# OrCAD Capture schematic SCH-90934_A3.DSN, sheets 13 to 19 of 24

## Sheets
13 C-09 IO MUX: size A2
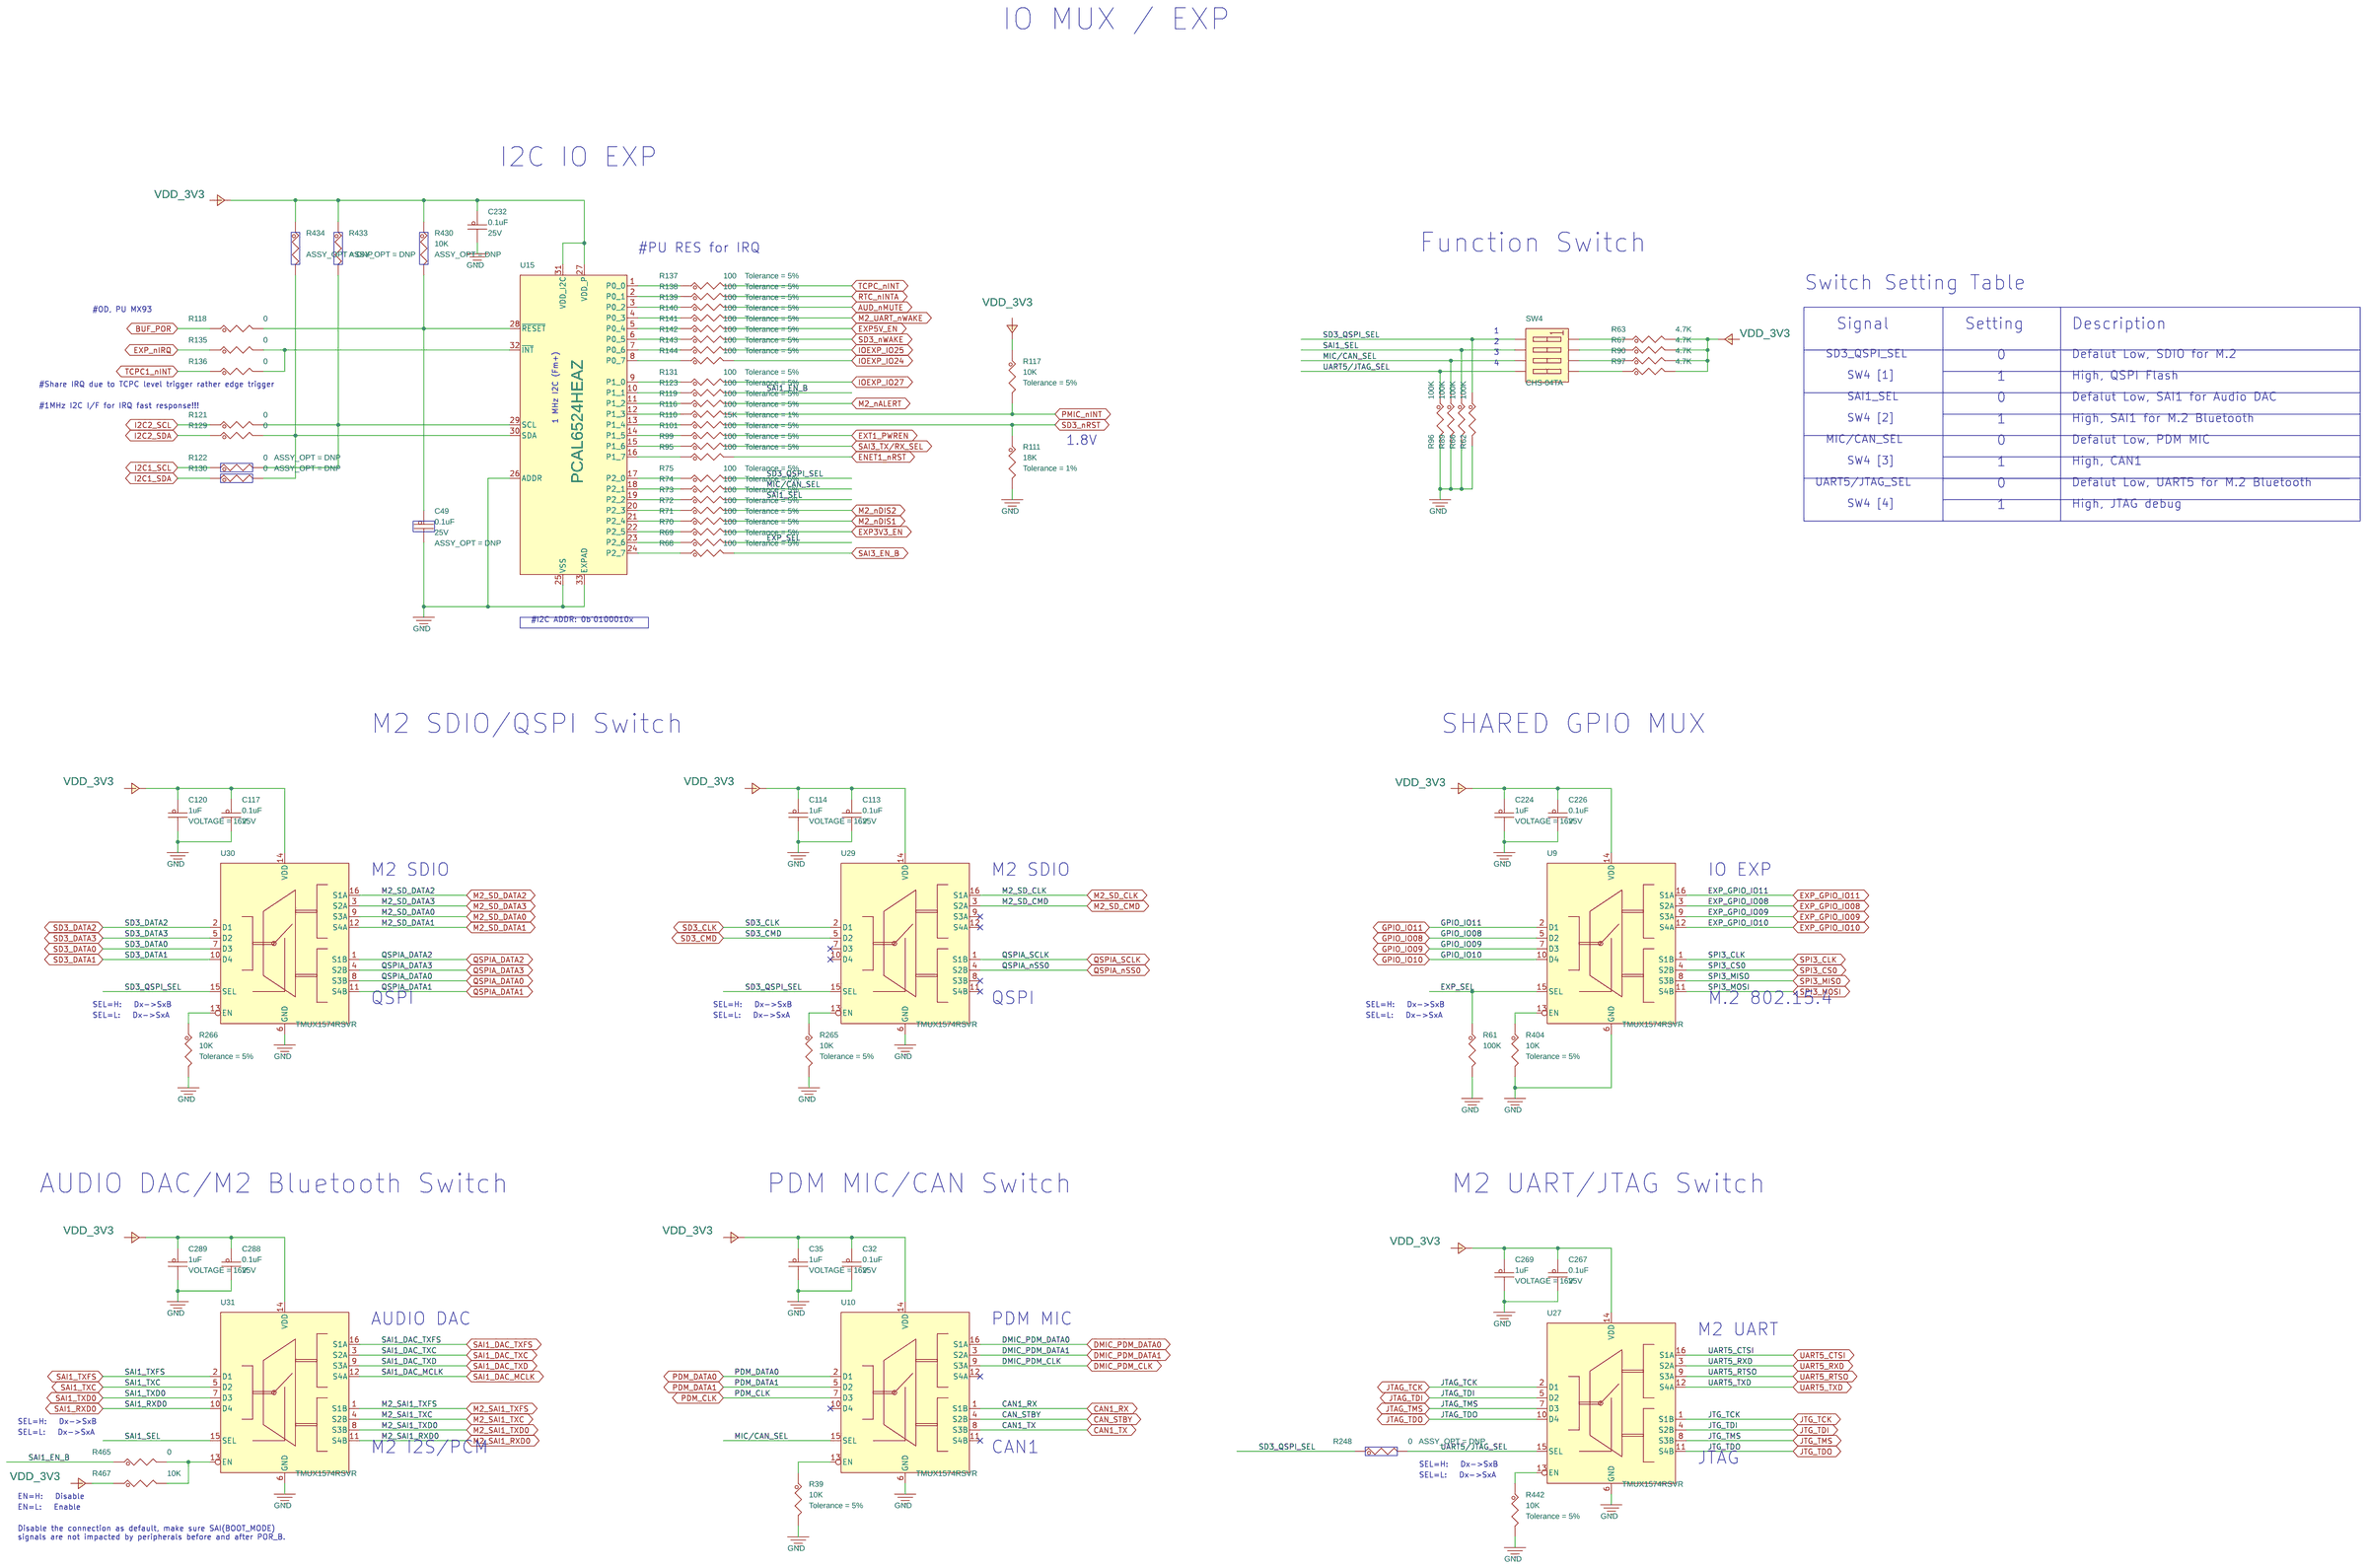
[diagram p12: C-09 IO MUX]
14 A-01 COVER: company: NXP Semiconductors
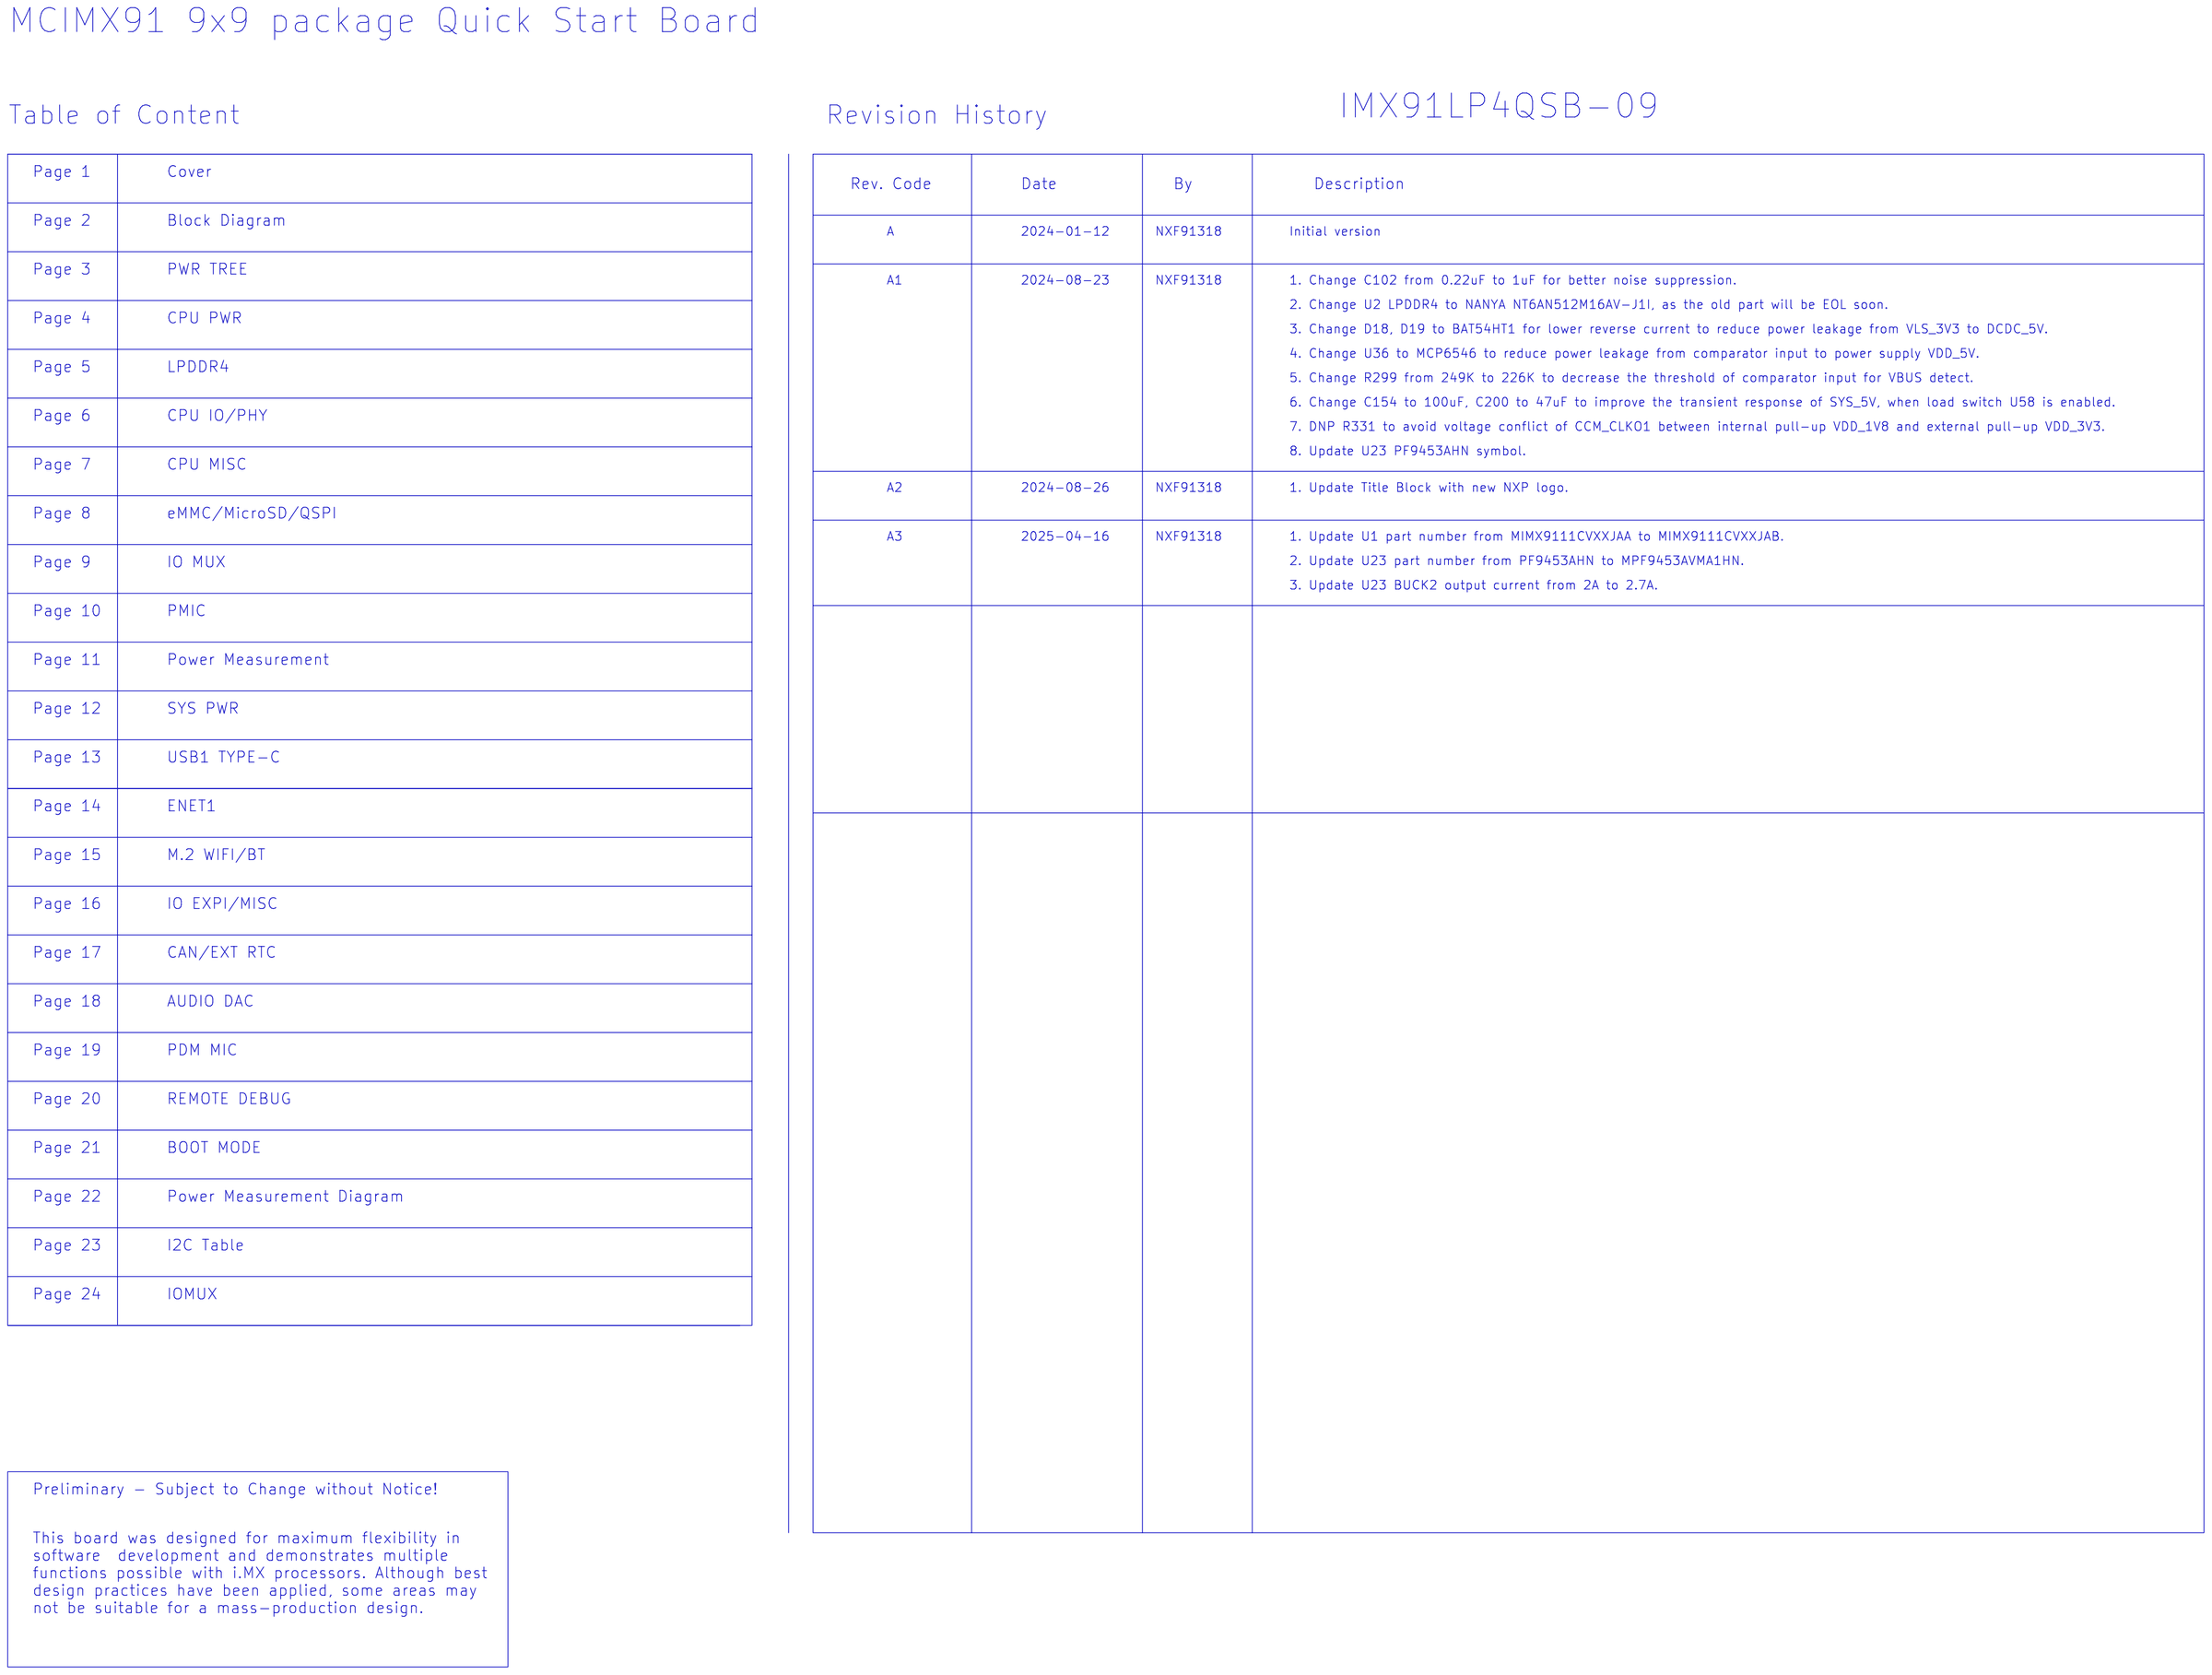
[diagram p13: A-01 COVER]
15 A-02 BLOCK DIAGRAM: company: NXP Semiconductors
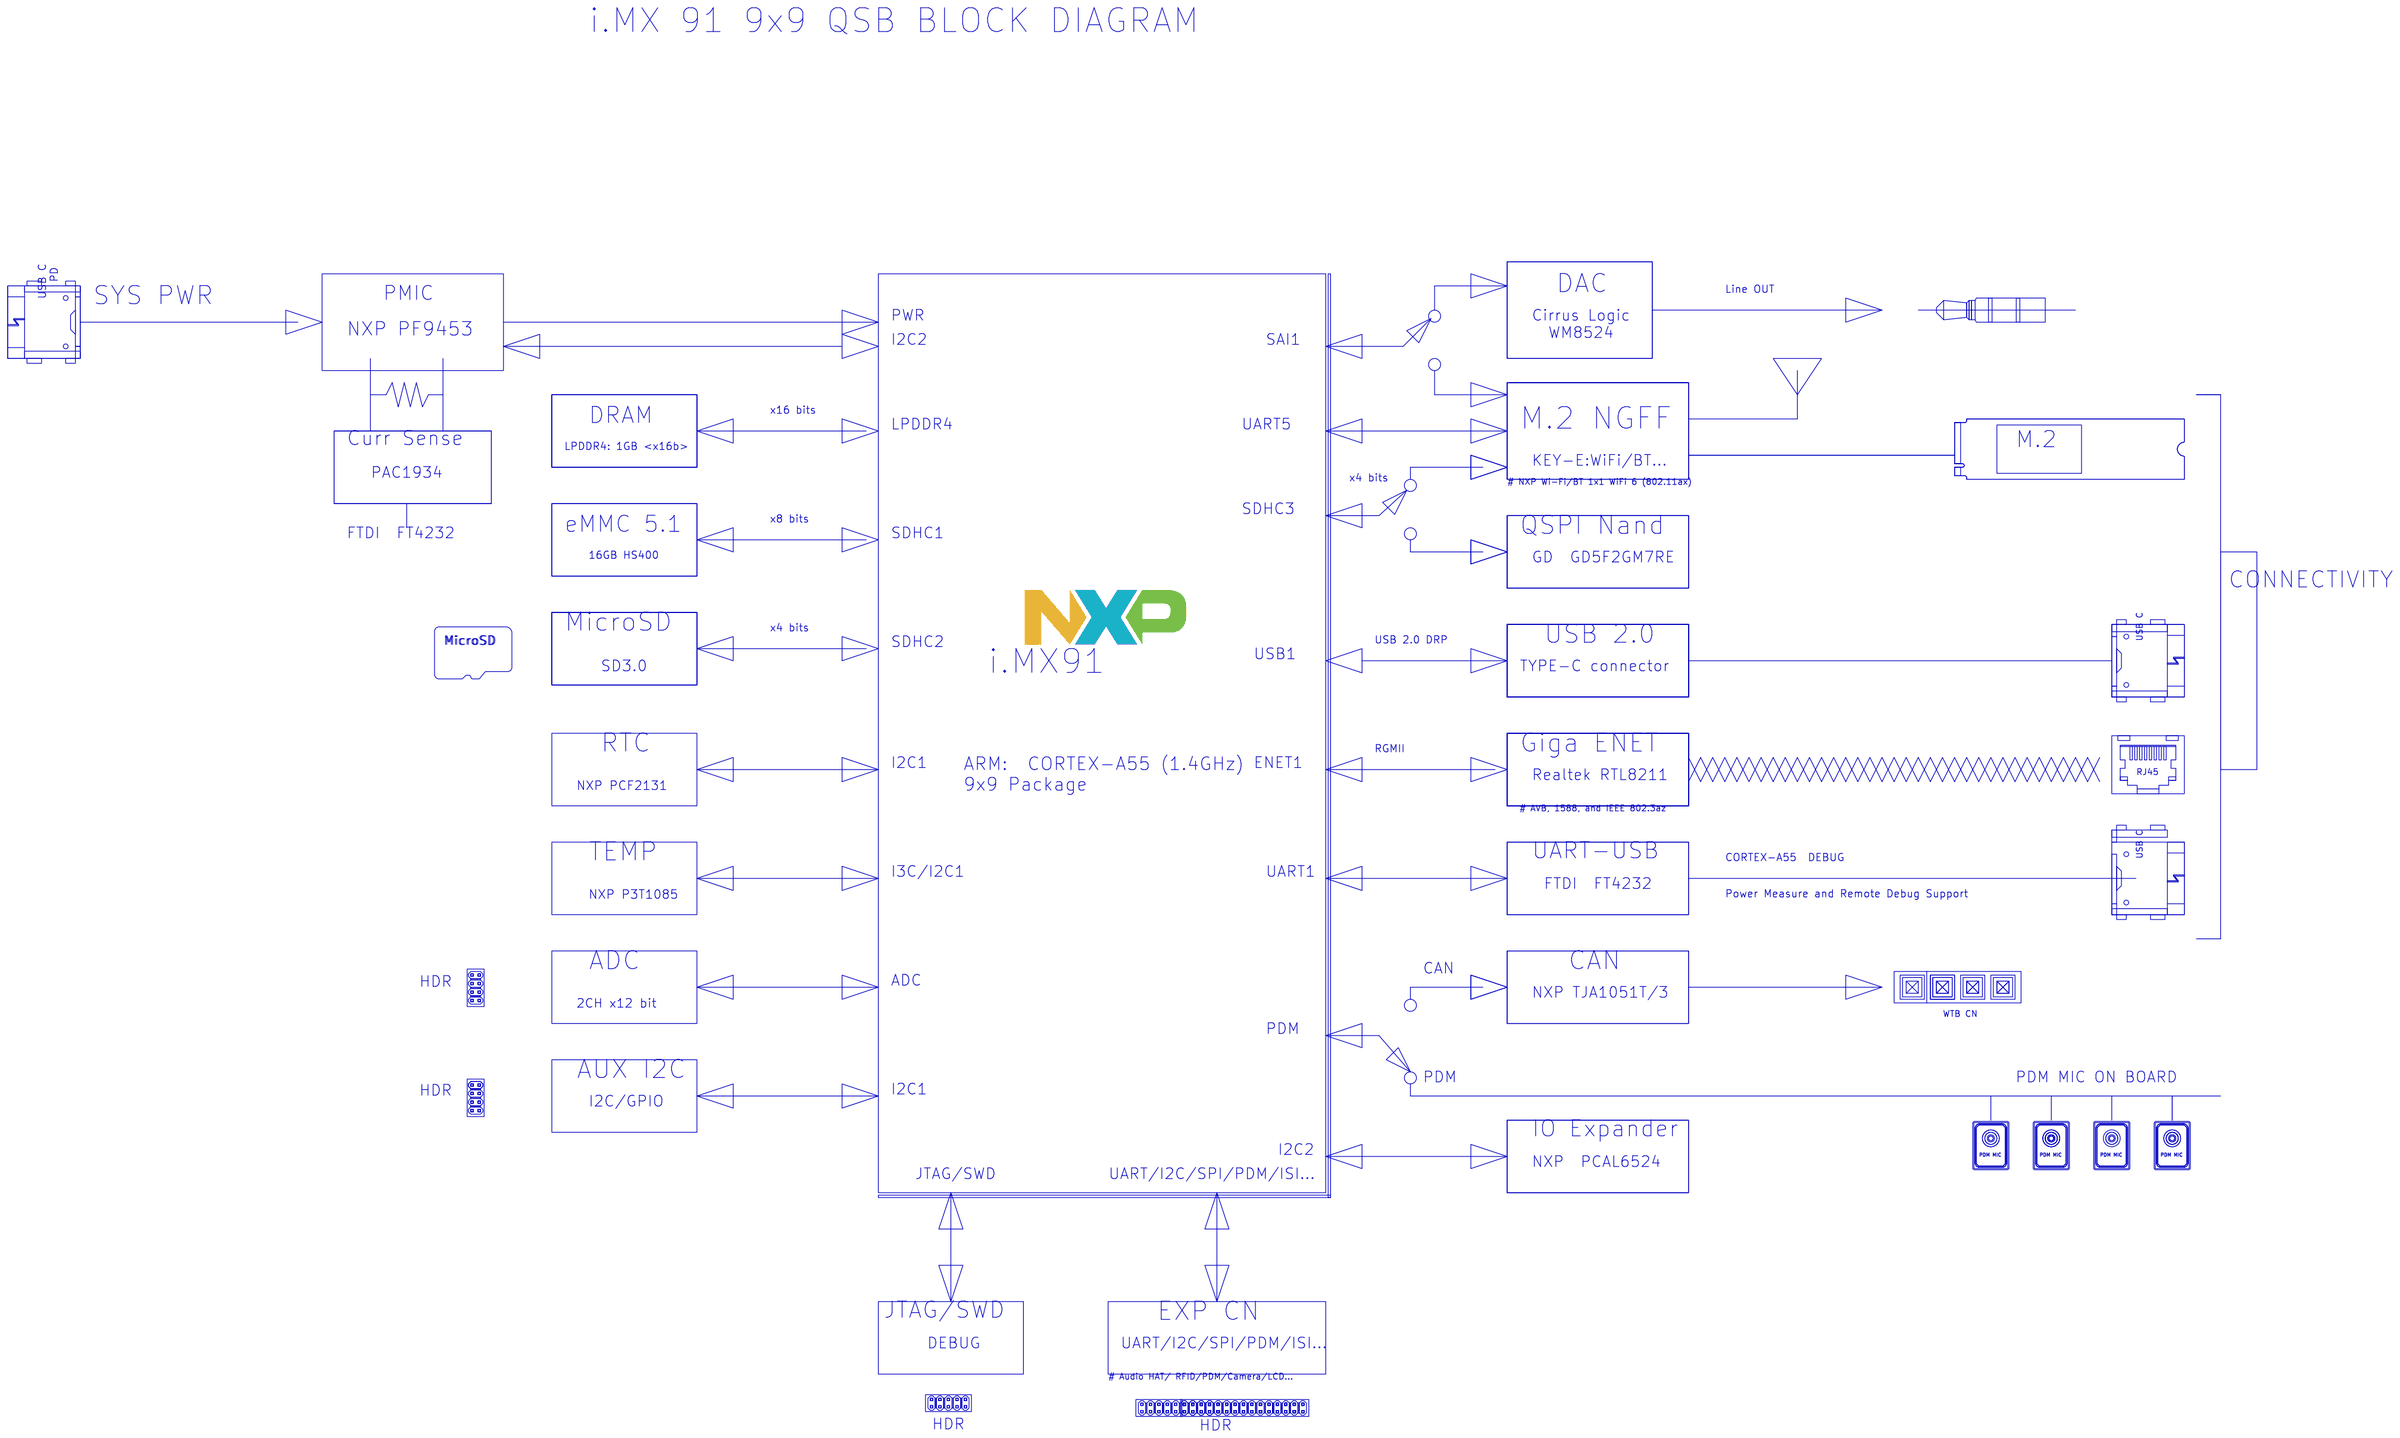
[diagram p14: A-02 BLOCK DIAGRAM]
16 A-03 PWR TREE: company: NXP Semiconductors
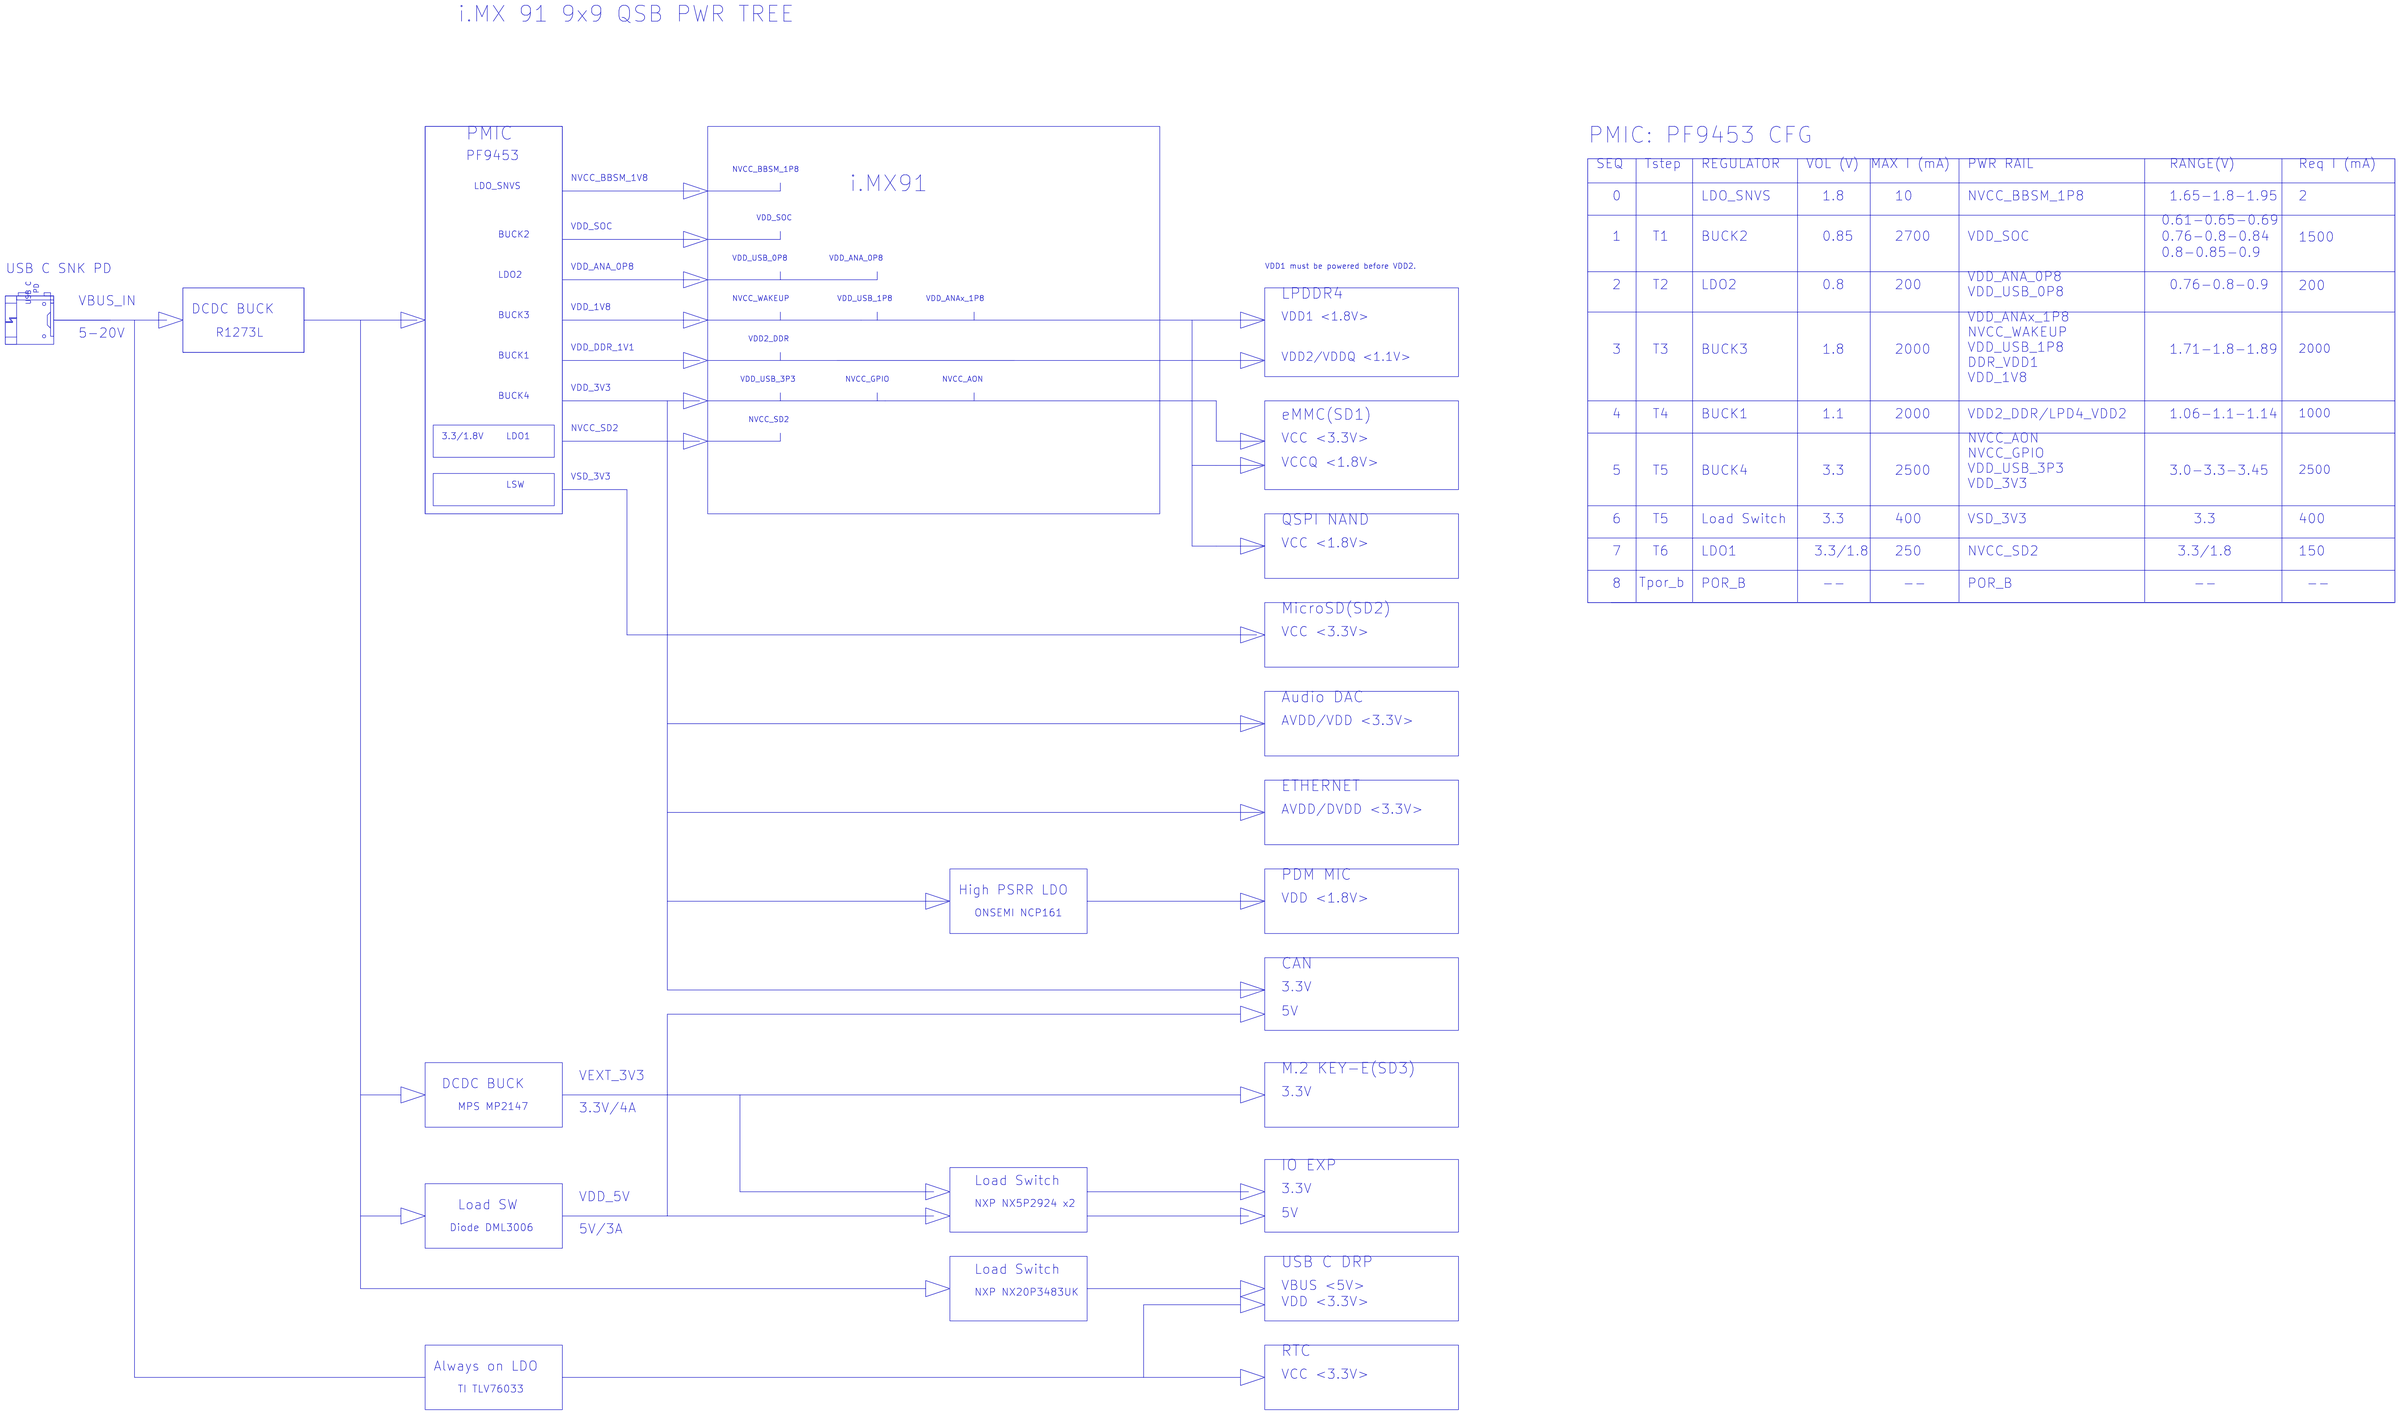
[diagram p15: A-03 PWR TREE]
17 C-04 CPU PWR: size C; company: NXP Semiconductors
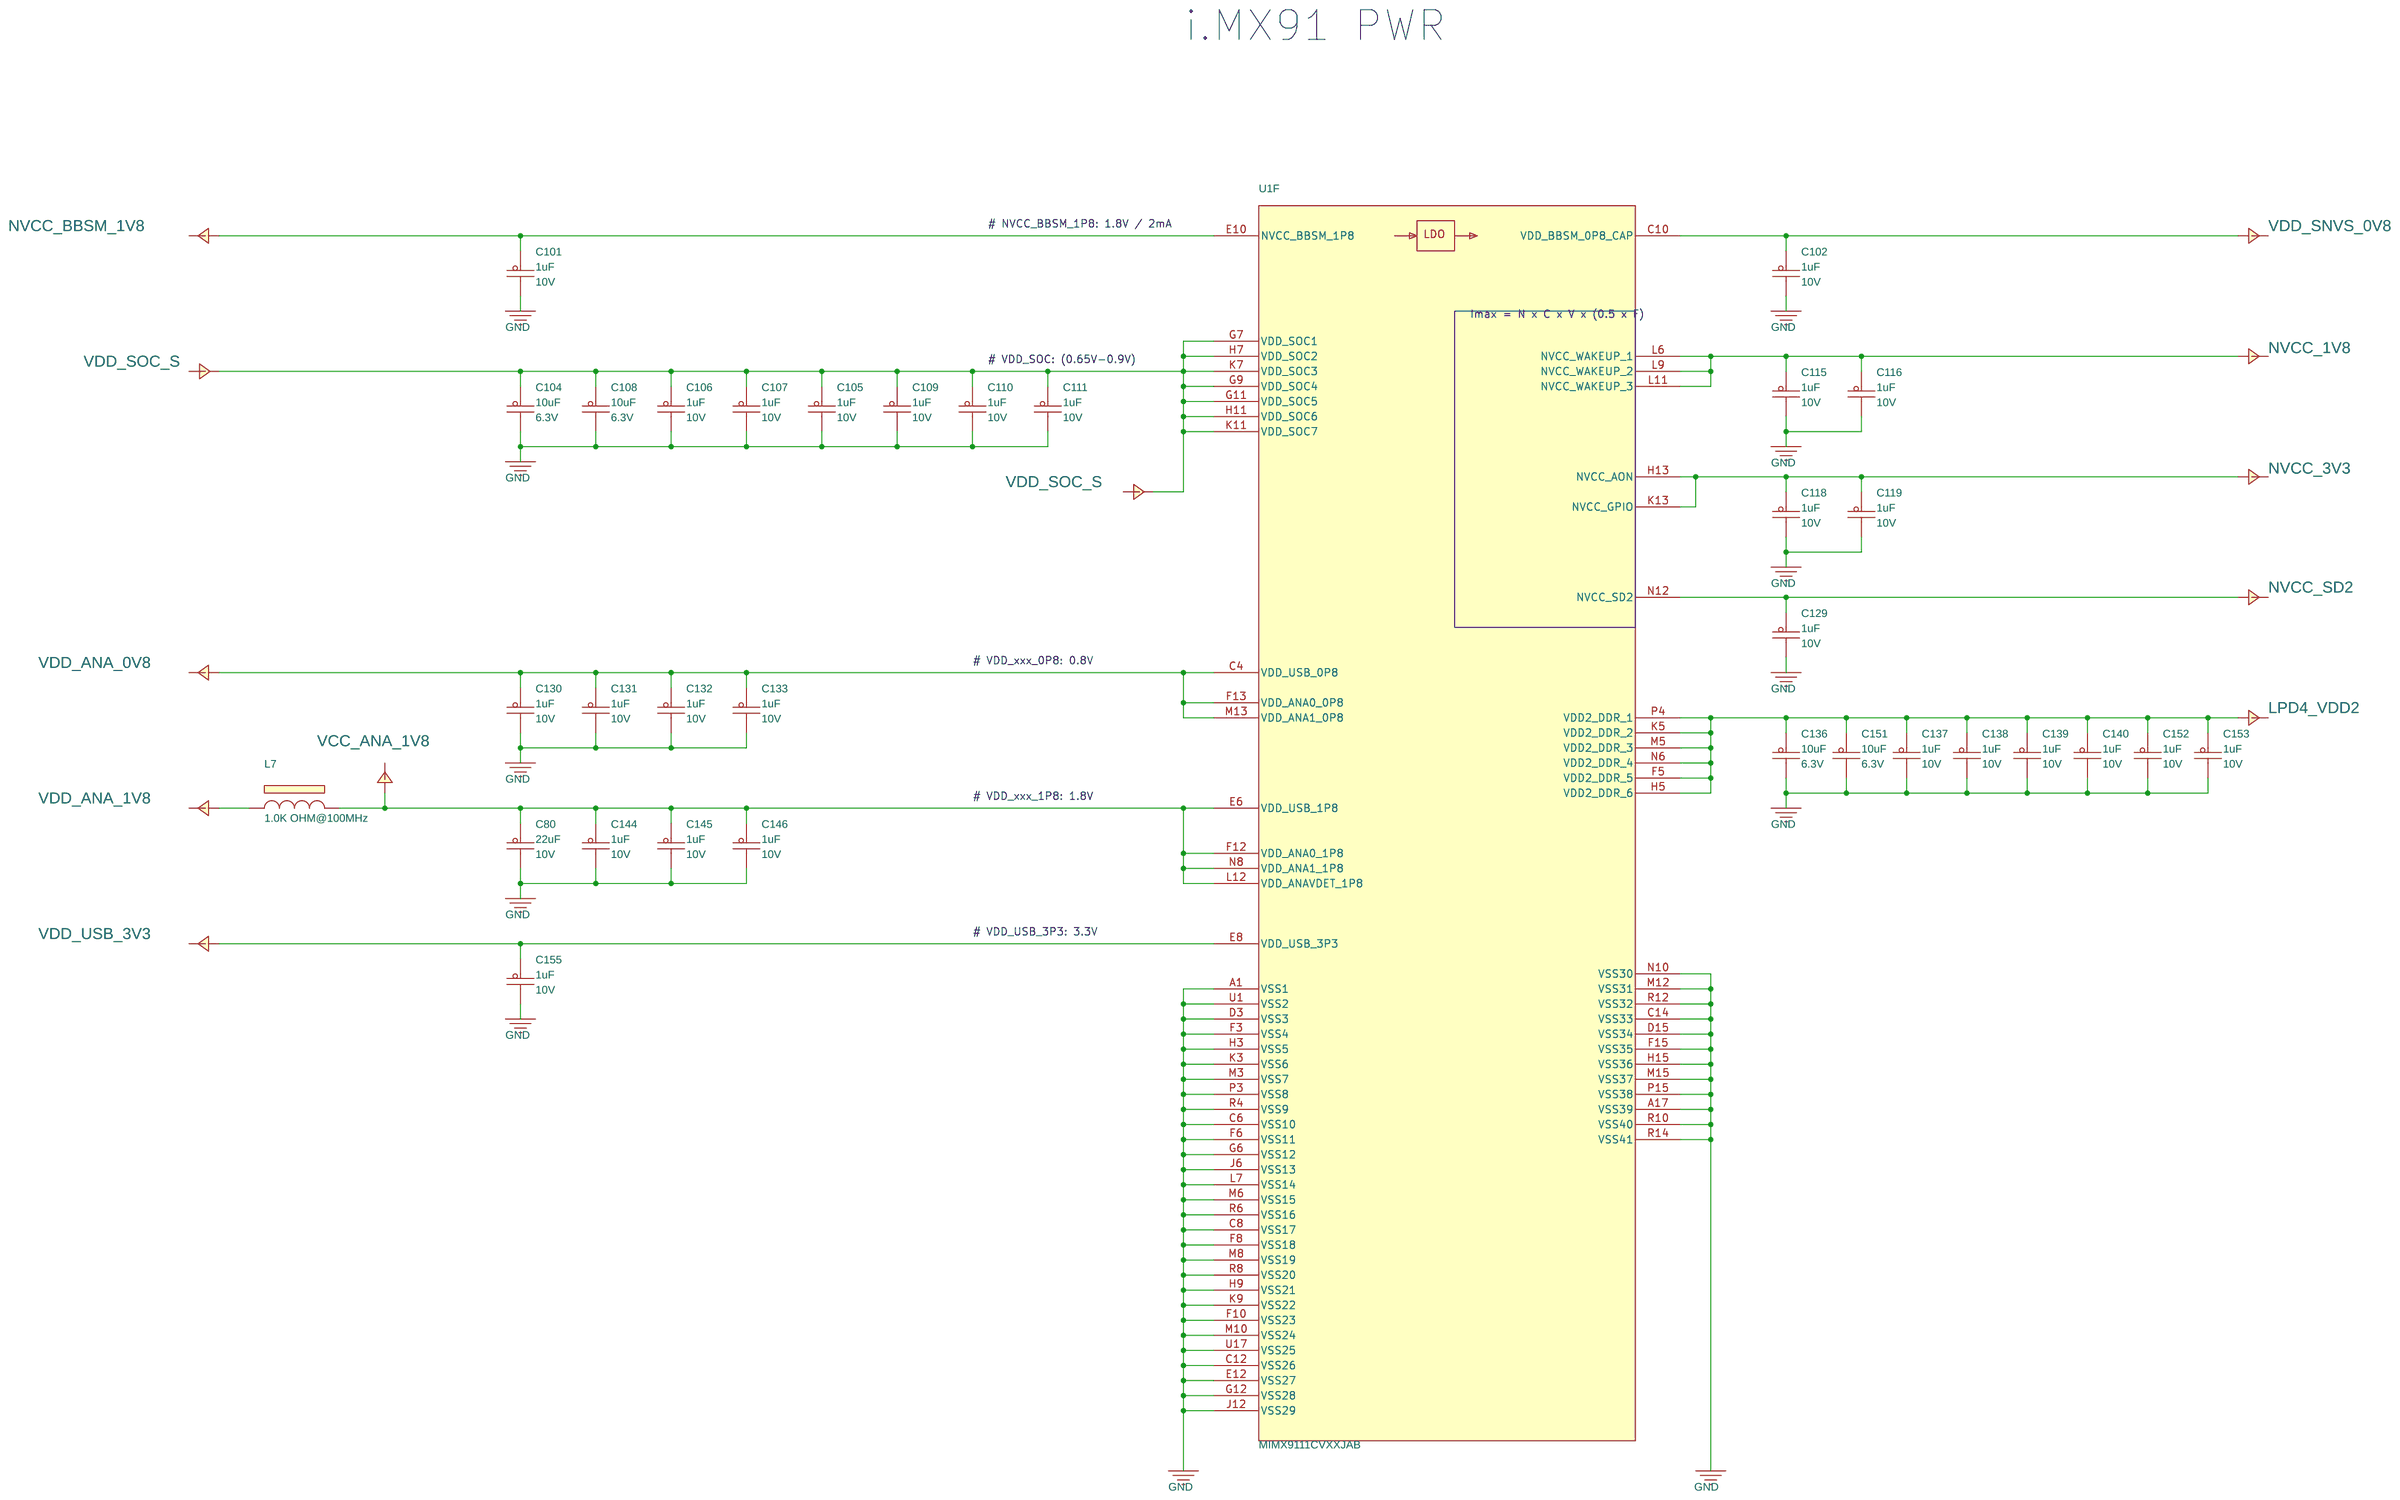
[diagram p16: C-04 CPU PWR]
18 C-05 LPDDR4: size C; company: NXP Semiconductors
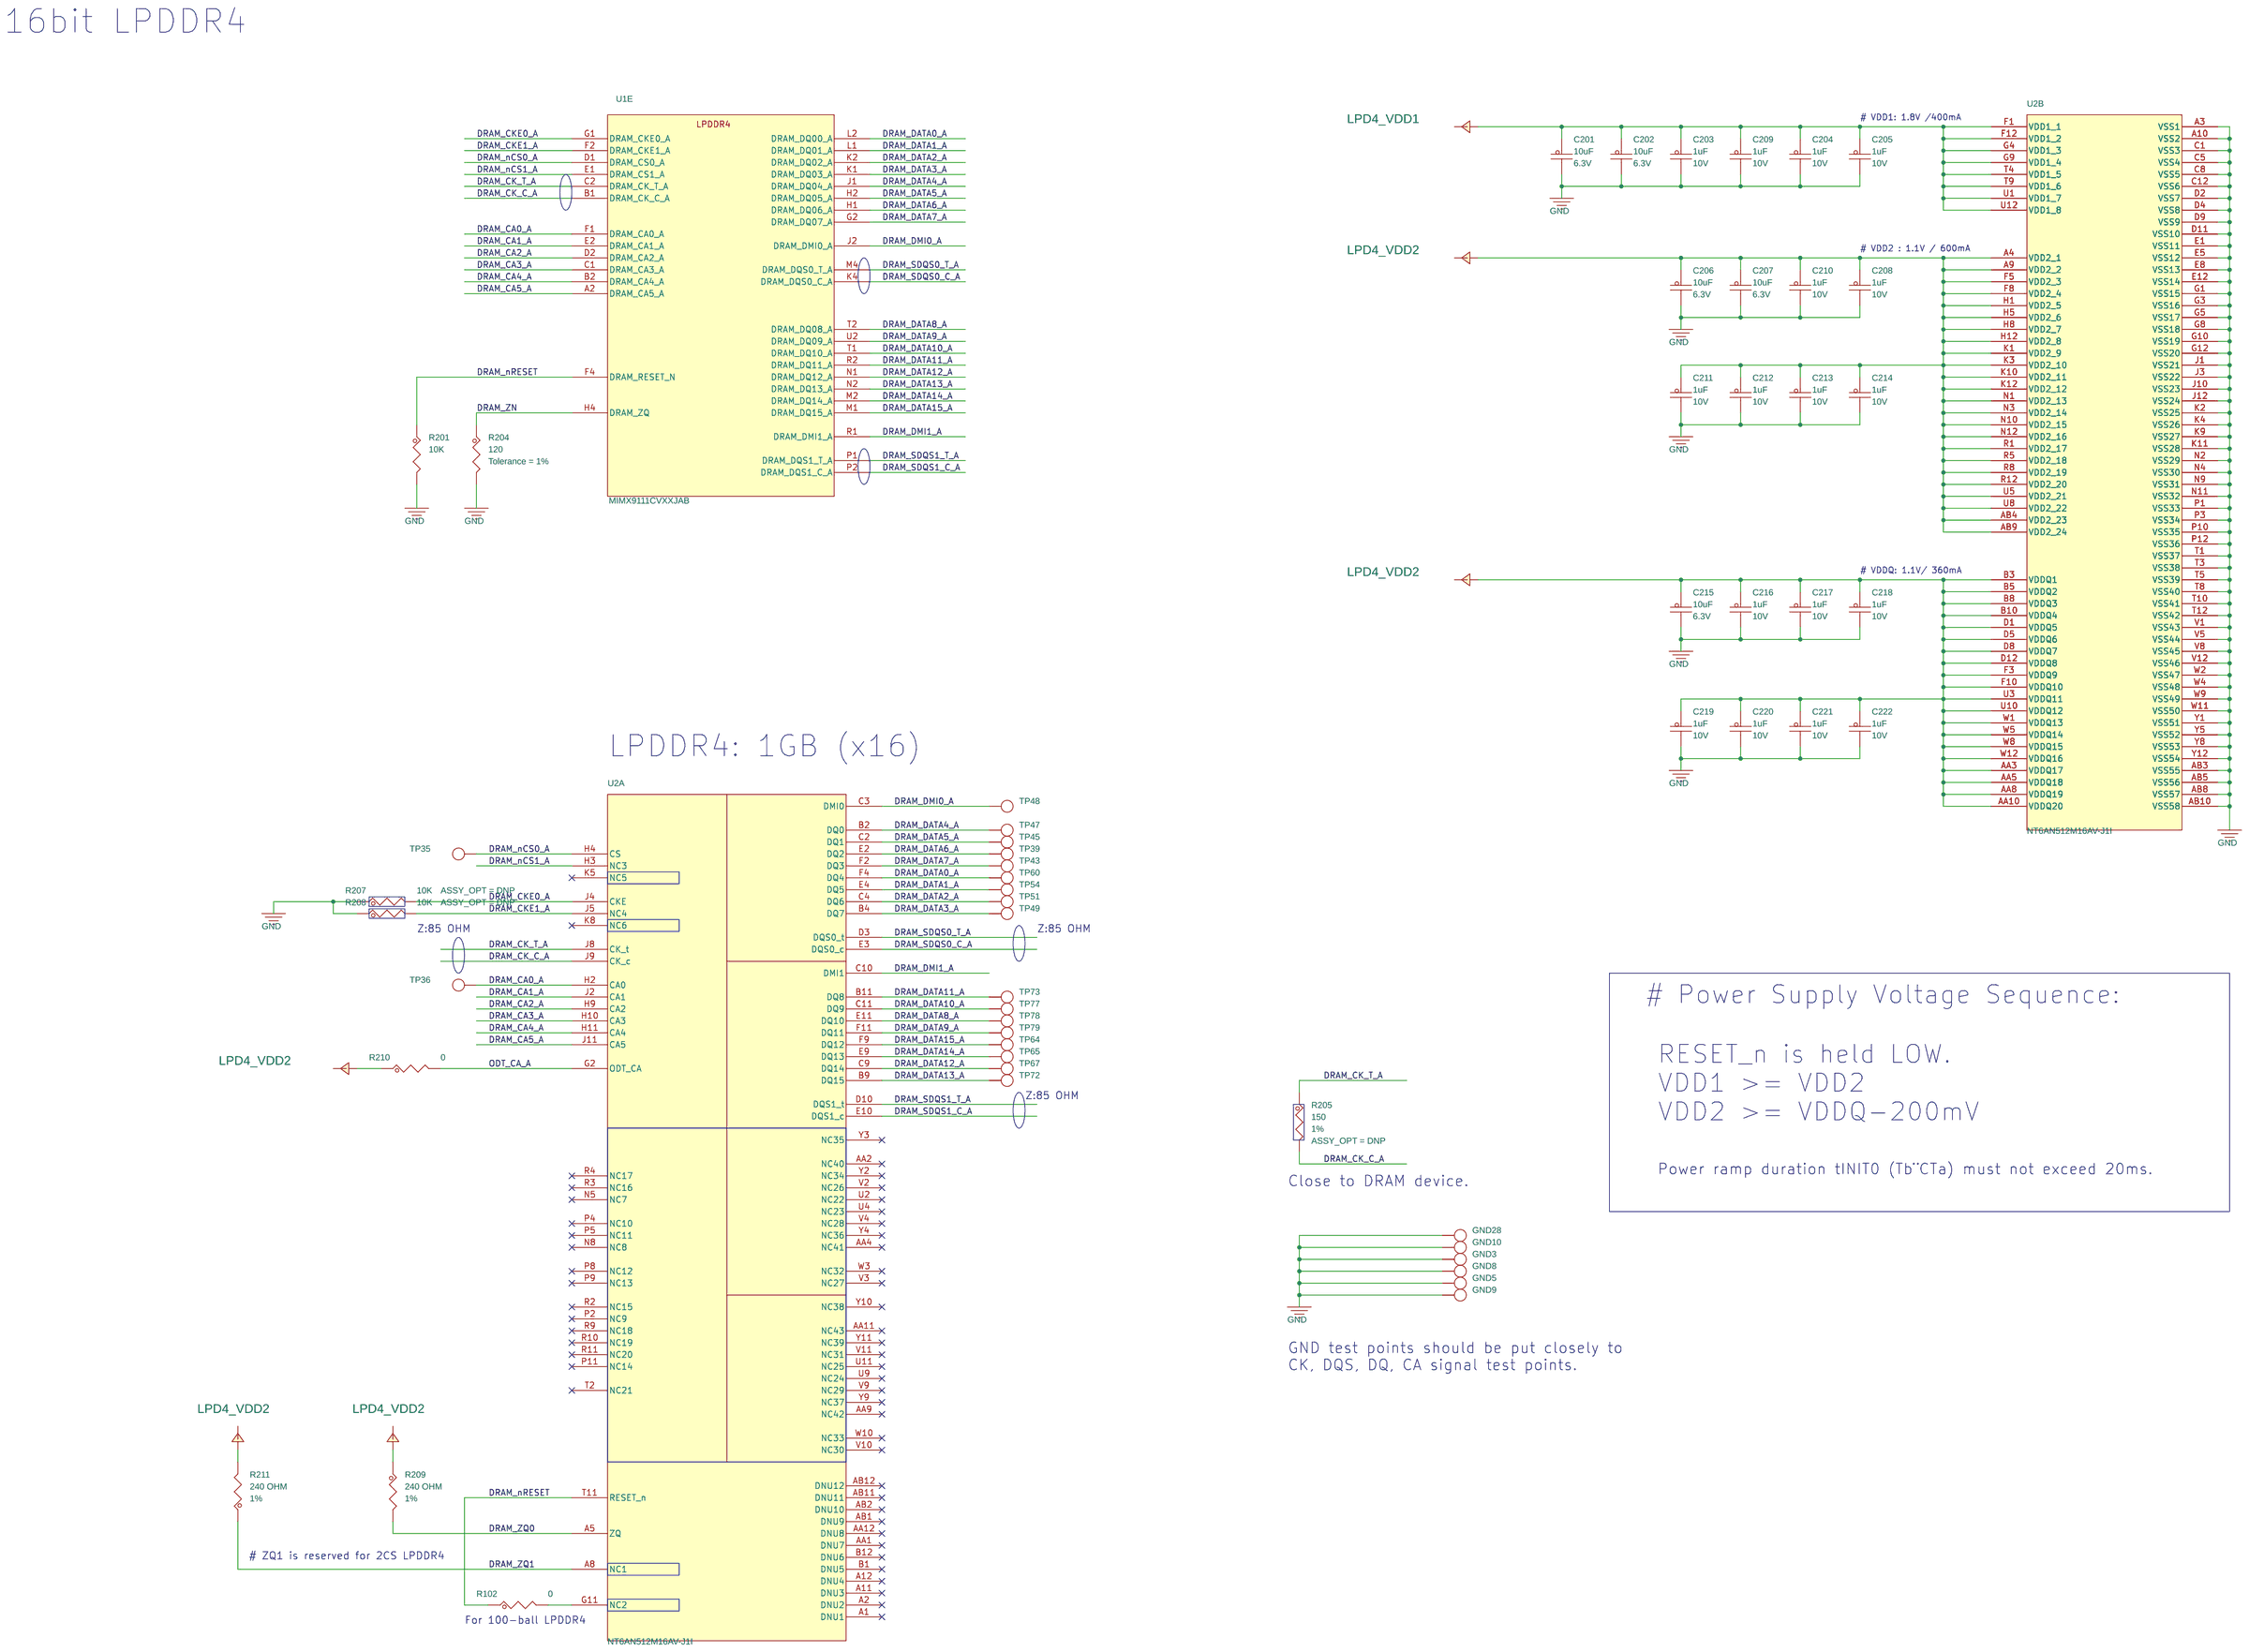
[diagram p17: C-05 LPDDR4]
19 C-10 PMIC: size C
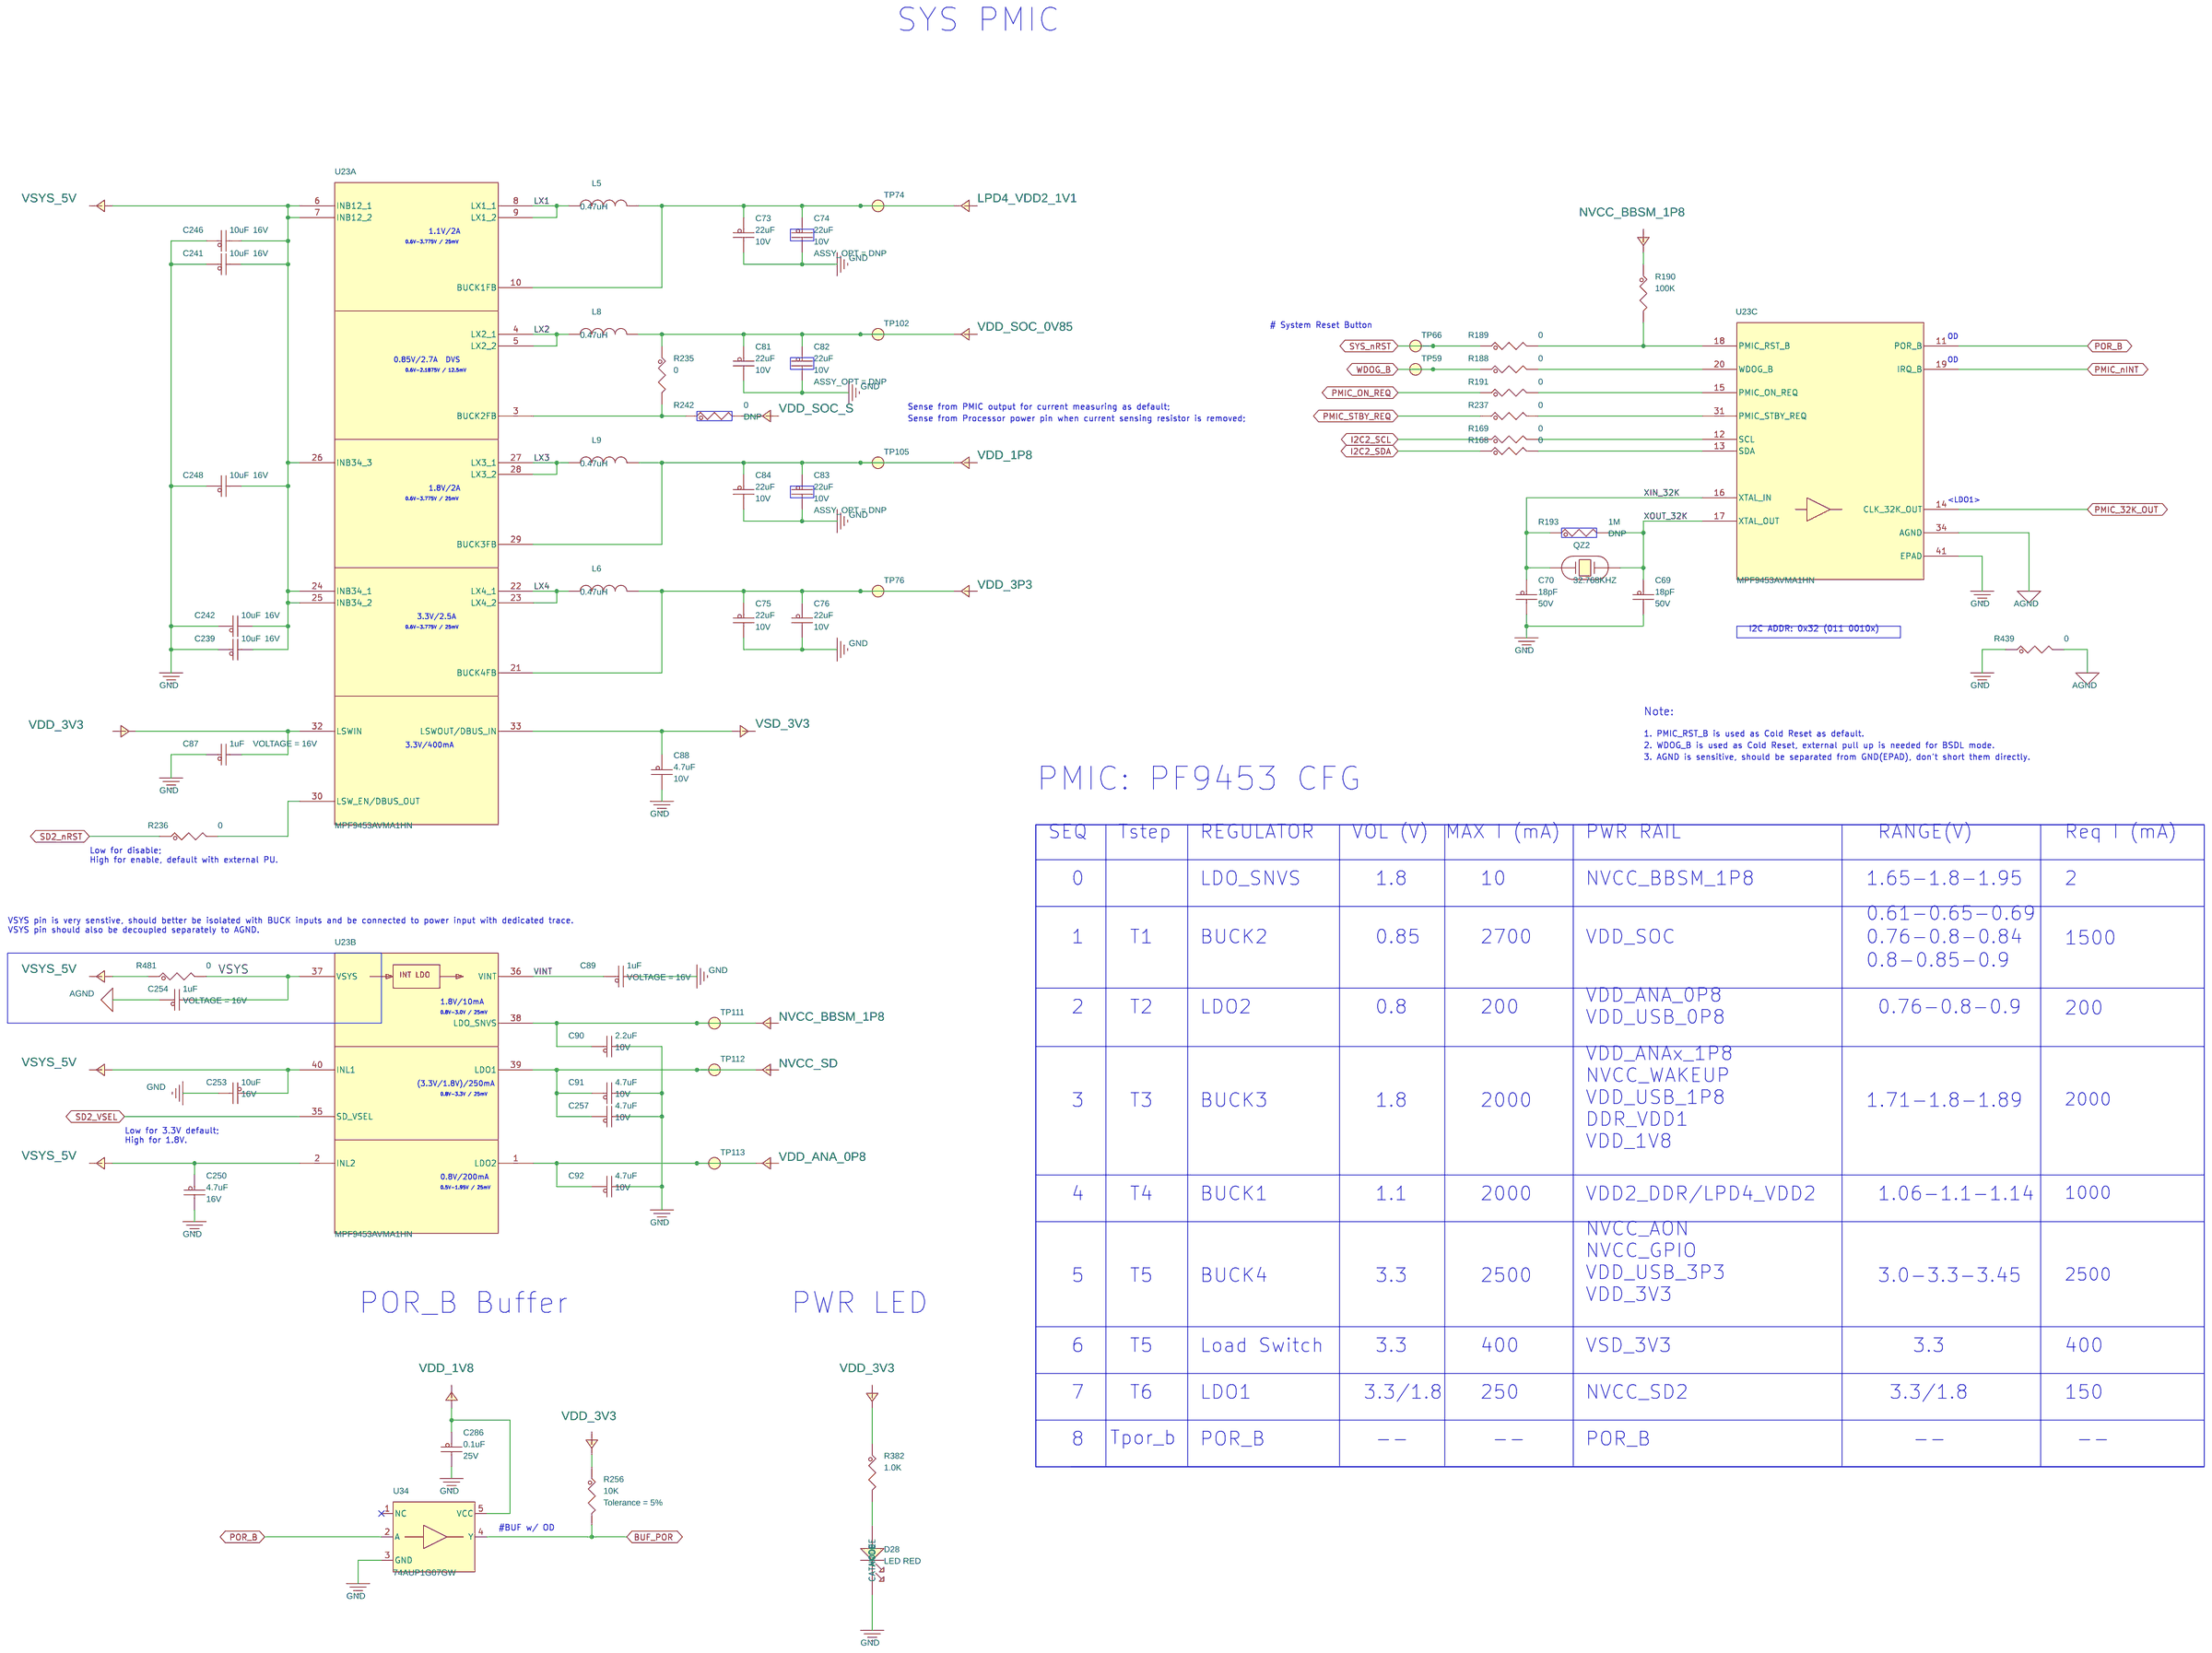
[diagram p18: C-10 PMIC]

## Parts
sheet C-04 CPU PWR
C80  22uF  [CC0603]
C101  1uF  [0201_CC]
C102  1uF  [0201_CC]
C104  10uF  [0402_cc_nsp]
C105  1uF  [0201_CC]
C106  1uF  [0201_CC]
C107  1uF  [0201_CC]
C108  10uF  [0402_cc_nsp]
C109  1uF  [0201_CC]
C110  1uF  [0201_CC]
C111  1uF  [0201_CC]
C115  1uF  [0201_CC]
C116  1uF  [0201_CC]
C118  1uF  [0201_CC]
C119  1uF  [0201_CC]
C129  1uF  [0201_CC]
C130  1uF  [0201_CC]
C131  1uF  [0201_CC]
C132  1uF  [0201_CC]
C133  1uF  [0201_CC]
C136  10uF  [0402_cc_nsp]
C137  1uF  [0201_CC]
C138  1uF  [0201_CC]
C139  1uF  [0201_CC]
C140  1uF  [0201_CC]
C144  1uF  [0201_CC]
C145  1uF  [0201_CC]
C146  1uF  [0201_CC]
C151  10uF  [0402_cc_nsp]
C152  1uF  [0201_CC]
C153  1uF  [0201_CC]
C155  1uF  [0201_CC]
L7  1.0K OHM@100MHz  [ind_0603]
sheet C-05 LPDDR4
C201  10uF  [0402_cc_nsp]
C202  10uF  [0402_cc_nsp]
C203  1uF  [0201_CC]
C204  1uF  [0201_CC]
C205  1uF  [0201_CC]
C206  10uF  [0402_cc_nsp]
C207  10uF  [0402_cc_nsp]
C208  1uF  [0201_CC]
C209  1uF  [0201_CC]
C210  1uF  [0201_CC]
C211  1uF  [0201_CC]
C212  1uF  [0201_CC]
C213  1uF  [0201_CC]
C214  1uF  [0201_CC]
C215  10uF  [0402_cc_nsp]
C216  1uF  [0201_CC]
C217  1uF  [0201_CC]
C218  1uF  [0201_CC]
C219  1uF  [0201_CC]
C220  1uF  [0201_CC]
C221  1uF  [0201_CC]
C222  1uF  [0201_CC]
GND3  TPAD_015  [TPAD_015]
GND5  TPAD_015  [TPAD_015]
GND8  TPAD_015  [TPAD_015]
GND9  TPAD_015  [TPAD_015]
GND10  TPAD_015  [TPAD_015]
GND28  TPAD_015  [TPAD_015]
R102  0  [0402_CC]
R201  10K  [0402_CC]
R204  120  [0402_CC]
R205  150  [0402_CC]
R207  10K  [0402_CC]
R208  10K  [0402_CC]
R209  240 OHM  [0201_CC]
R210  0  [0402_CC]
R211  240 OHM  [0201_CC]
TP35  TPAD_015  [TPAD_015]
TP36  TPAD_015  [TPAD_015]
TP39  TPAD_015  [TPAD_015]
TP43  TPAD_015  [TPAD_015]
TP45  TPAD_015  [TPAD_015]
TP47  TPAD_015  [TPAD_015]
TP48  TPAD_015  [TPAD_015]
TP49  TPAD_015  [TPAD_015]
TP51  TPAD_015  [TPAD_015]
TP54  TPAD_015  [TPAD_015]
TP60  TPAD_015  [TPAD_015]
TP64  TPAD_015  [TPAD_015]
TP65  TPAD_015  [TPAD_015]
TP67  TPAD_015  [TPAD_015]
TP72  TPAD_015  [TPAD_015]
TP73  TPAD_015  [TPAD_015]
TP77  TPAD_015  [TPAD_015]
TP78  TPAD_015  [TPAD_015]
TP79  TPAD_015  [TPAD_015]
U2  NT6AN512M16AV-J1I  [bga200_0p65x0p8_10p1x14p6]  (sections A,B)
sheet C-07 CPU MISC
U1  MIMX9111CVXXJAB  [pbga208_0p5_9x9mm_sm]  (sections A,B,C,D,E,F)
sheet C-09 IO MUX
C32  0.1uF  [CC0402_25]
C35  1uF  [CC0402_25]
C49  0.1uF  [CC0402_25]
C113  0.1uF  [CC0402_25]
C114  1uF  [CC0402_25]
C117  0.1uF  [CC0402_25]
C120  1uF  [CC0402_25]
C224  1uF  [CC0402_25]
C226  0.1uF  [CC0402_25]
C232  0.1uF  [CC0402_25]
C267  0.1uF  [CC0402_25]
C269  1uF  [CC0402_25]
C288  0.1uF  [CC0402_25]
C289  1uF  [CC0402_25]
R39  10K  [0402_CC]
R61  100K  [0402_CC]
R62  100K  [0402_CC]
R63  4.7K  [RC0402_25]
R66  100K  [0402_CC]
R67  4.7K  [RC0402_25]
R68  100  [RC0402_25]
R69  100  [RC0402_25]
R70  100  [RC0402_25]
R71  100  [RC0402_25]
R72  100  [RC0402_25]
R73  100  [RC0402_25]
R74  100  [RC0402_25]
R75  100  [RC0402_25]
R89  100K  [0402_CC]
R90  4.7K  [RC0402_25]
R95  100  [RC0402_25]
R96  100K  [0402_CC]
R97  4.7K  [RC0402_25]
R99  100  [RC0402_25]
R101  100  [RC0402_25]
R110  15K  [RC0402_25]
R111  18K  [RC0402_25]
R116  100  [RC0402_25]
R117  10K  [0402_CC]
R118  0  [0402_CC]
R119  100  [RC0402_25]
R121  0  [0402_CC]
R122  0  [0402_CC]
R123  100  [RC0402_25]
R129  0  [0402_CC]
R130  0  [0402_CC]
R131  100  [RC0402_25]
R135  0  [0402_CC]
R136  0  [0402_CC]
R137  100  [RC0402_25]
R138  100  [RC0402_25]
R139  100  [RC0402_25]
R140  100  [RC0402_25]
R141  100  [RC0402_25]
R142  100  [RC0402_25]
R143  100  [RC0402_25]
R144  100  [RC0402_25]
R248  0  [0402_CC]
R265  10K  [0402_CC]
R266  10K  [0402_CC]
R404  10K  [0402_CC]
R430  10K  [0402_CC]
R433  2.2K  [0402_CC]
R434  2.2K  [0402_CC]
R442  10K  [0402_CC]
R465  0  [0402_CC]
R467  10K  [0402_CC]
SW4  CHS-04TA  [sw_chs_04_a]
U9  TMUX1574RSVR  [pqfn16_0p4_2p65x1p85]
U10  TMUX1574RSVR  [pqfn16_0p4_2p65x1p85]
U15  PCAL6524HEAZ  [uqfn32_0p5_5x5_ep3x3]
U27  TMUX1574RSVR  [pqfn16_0p4_2p65x1p85]
U29  TMUX1574RSVR  [pqfn16_0p4_2p65x1p85]
U30  TMUX1574RSVR  [pqfn16_0p4_2p65x1p85]
U31  TMUX1574RSVR  [pqfn16_0p4_2p65x1p85]
sheet C-10 PMIC
C69  18pF  [0201_CC]
C70  18pF  [0201_CC]
C73  22uF  [CC0603]
C74  22uF  [CC0603]
C75  22uF  [CC0603]
C76  22uF  [CC0603]
C81  22uF  [CC0603]
C82  22uF  [CC0603]
C83  22uF  [CC0603]
C84  22uF  [CC0603]
C87  1uF  [CC0402_25]
C88  4.7uF  [cc0402_tol0p15]
C89  1uF  [CC0402_25]
C90  2.2uF  [CC0402_25]
C91  4.7uF  [cc0402_tol0p15]
C92  4.7uF  [cc0402_tol0p15]
C239  10uF  [CC0603]
C241  10uF  [CC0603]
C242  10uF  [CC0603]
C246  10uF  [CC0603]
C248  10uF  [CC0603]
C250  4.7uF  [CC0603]
C253  10uF  [CC0603]
C254  1uF  [CC0402_25]
C257  4.7uF  [cc0402_tol0p15]
C286  0.1uF  [CC0402_25]
D28  LED RED  [LED_0603]
L5  0.47uH  [IND_2016A]
L6  0.47uH  [IND_2016A]
L8  0.47uH  [IND_2016A]
L9  0.47uH  [IND_2016A]
QZ2  32.768KHZ  [XTAL2-3P2X1P5-SM]
R168  0  [0402_CC]
R169  0  [0402_CC]
R188  0  [0402_CC]
R189  0  [0402_CC]
R190  100K  [0402_CC]
R191  0  [0402_CC]
R193  1M  [0201_CC]
R235  0  [0402_CC]
R236  0  [0402_CC]
R237  0  [0402_CC]
R242  0  [0402_CC]
R256  10K  [0402_CC]
R382  1.0K  [0402_CC]
R439  0  [0402_CC]
R481  0  [0402_CC]
TP59  TP_35MIL  [testpoint_35mil]
TP66  TP_35MIL  [testpoint_35mil]
TP74  TP_35MIL  [testpoint_35mil]
TP76  TP_35MIL  [testpoint_35mil]
TP102  TP_35MIL  [testpoint_35mil]
TP105  TP_35MIL  [testpoint_35mil]
TP111  TP_35MIL  [testpoint_35mil]
TP112  TP_35MIL  [testpoint_35mil]
TP113  TP_35MIL  [testpoint_35mil]
U23  MPF9453AVMA1HN  [qfn40_0p4_5x5_ep146x146]  (sections A,B,C)
U34  74AUP1G07GW  [sc70-5]

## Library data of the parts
C73 C75 C76 C80 C81 C84 = CAP_NP: CAP CER 22uF 10V 20% X5R 0603; AGILE_PN: 150-79530; CAD_APPROVED: Yes; FPLIST: CC0603_OV,CC0603,0603_cc_tol; HEIGHT: 1MM; MFG_NAME01: SAMSUNG; MFG_PN01: CL10A226MP7LUNC; Package Size: 0603; ROHS: Yes; Rated Voltage: 10V; SIGNAL_MODEL: DEFAULT_CAPACITOR_2.2e+07pF_2_1; Temp Range: -55C to +85C; Tolerance: 20%; VOLTAGE: 10V; WVDC: 6.3V
C101 C102 C105-C107 C109-C111 C115 C116 C118 C119 C129-C133 C137-C140 C144-C146 C152 C153 C155 C203-C205 C208-C214 C216-C222 = CAP_NP: CAP CER 1.0uF 10V 10% X5R 0201; AGILE_PN: 150-81088; CAD_APPROVED: Yes; FPLIST: CC0201,CC0201_HD,0201_CC,cc_0201_cir; HEIGHT: 0.35MM; MFG_NAME01: SAMSUNG ELECTRO MECHANICS; MFG_PN01: CL03A105KP3NSNC; Package Size: 0201 (0603 Metric); Package Type: SMD/SMT; ROHS: Yes; Rated Voltage: 10V; Temp Range: -55C to +85C; Tolerance: 10%; VOLTAGE: 10V
C104 C108 C136 C151 C201 C202 C206 C207 C215 = CAP_NP: CAP CER 10UF 6.3V 20% X5R 0402; 3D_Mechanical_Footprint_File: cc0402_tol0p2; AGILE_PN: 150-79163; CAD_APPROVED: Yes; FPLIST: CC0402_25,CC0402_HD,0402_CC; HEIGHT: 0.7 MM; MFG_NAME01: SAMSUNG ELECTRO MECHANICS; MFG_PN01: CL05A106MQ5NUNC; ROHS: Yes; Rated Voltage: 6.3V; Temp Range: -55C to +85C; Tolerance: 20%; VOLTAGE: 6.3V
L7 = INDUCTOR_FERRITE: IND FER BEAD 1.0K OHM@100MHz 1.2A 25% 0603; 3D_Mechanical_Footprint_File: http://fcl.am.freescale.net/ALLEGRO/step/ind_0603.STEP; AGILE_PN: 180-81296; CAD_APPROVED: Yes; FPLIST: ind_0603,0603_cc; HEIGHT: 0.95; MFG_NAME01: MURATA; MFG_PN01: BLM18SP102SN1D; Package Size: 0603 (1608 Metric); ROHS: Yes; Temp Range: -55°C to +125°C
GND3 GND5 GND8-GND10 GND28 TP35 TP36 TP39 TP43 TP45 TP47-TP49 TP51 TP54 TP60 TP64 TP65 TP67 TP72 TP73 TP77-TP79 = TESTLOOP: TEST POINT PAD 15MIL DIA SMT, NO PART TO ORDER; AGILE_PN: 211-76645; ASSY_OPT: DNP; CAD_APPROVED: Yes; HEIGHT: 0.1MM; MFG_NAME01: NOTACOMPONENT; MFG_PN01: NOTACOMPONENT; ROHS: Yes
R102 R118 R121 R129 R135 R136 R168 R169 R188 R189 R191 R210 R235-R237 R439 R465 R481 = RES: RES MF ZERO OHM 1/16W 5% 0402; AGILE_PN: 470-75394; CAD_APPROVED: Yes; FPLIST: RC0402_25,RC0402_HD,RC0402_X2,0402_CC; HEIGHT: 0.45; MFG_NAME01: YAGEO AMERICA; MFG_PN01: RC0402JR-070RL; ROHS: Yes; Temp Range: -55 to +155C; Tolerance: 5%; VOLTAGE: 1/16W
R39 R117 R201 R256 R265 R266 R404 R442 R467 = RES: RES MF 10K 1/16W 5% 0402; AGILE_PN: 470-75557; CAD_APPROVED: Yes; FPLIST: RC0402_25,RC0402_HD,0402_CC; HEIGHT: 0.4 MM; MFG_NAME01: VISHAY INTERTECHNOLOGY; MFG_PN01: CRCW040210K0JNED; ROHS: Yes; Tolerance: 5%
R204 = RES: RES MF 120 OHM 1/10W 1% AEC-Q200 0402; AGILE_PN: 470-82646; CAD_APPROVED: Yes; FPLIST: RC0402_25,RC0402_HD,0402_CC; HEIGHT: 0.4MM; MFG_NAME01: Panasonic; MFG_PN01: ERJ-2RKF1200X; ROHS: Yes; Temp Range: -55°C ~ 155°C; Tolerance: 1%; VOLTAGE: 1/10W
R205 = RES: RES MF 150 OHM 1/16W 1% 0402; AGILE_PN: 470-75353; ASSY_OPT: DNP; CAD_APPROVED: Yes; FPLIST: RC0402_25,RC0402_HD,0402_CC; HEIGHT: 0.4MM; MFG_NAME01: NIC COMPONENTS CORP; MFG_PN01: NRCL04F1500TRF; ROHS: Yes; Tolerance: 1%
R207 R208 R430 = RES: RES MF 10K 1/16W 5% 0402; AGILE_PN: 470-75557; ASSY_OPT: DNP; CAD_APPROVED: Yes; FPLIST: RC0402_25,RC0402_HD,0402_CC; HEIGHT: 0.4 MM; MFG_NAME01: VISHAY INTERTECHNOLOGY; MFG_PN01: CRCW040210K0JNED; ROHS: Yes; Tolerance: 5%
R209 R211 = RES: RES MF 240 OHM 1/20W 1% 0201; AGILE_PN: 470-81317; CAD_APPROVED: Yes; FPLIST: CC0201,CC0201_HD,0201_CC; HEIGHT: 0.26MM; MFG_NAME01: YAGEO AMERICA; MFG_PN01: RC0201FR-07240RL; ROHS: Yes; Temp Range: -55°C ~ 125°C; Temp_Range: -55°C ~ 125°C; Tolerance: 1%; VOLTAGE: 25V
U2 = MT53E128M16D1DS_200P_A: IC MEM LPDDR4 SDRAM 512MbX16 1.1V WFBGA200; 3D_Mechanical_Footprint_File: http://fcl.am.freescale.net/ALLEGRO/step/bga200_0p65x0p8_10p1x15p1.step; AGILE_PN: TMP-CIP-16898; CAD_APPROVED: Yes; HEIGHT: 1.0MM; MFG_NAME01: NAN-YA; PRE_APN: 334-10018; ROHS: NULL; Temp Range: -30C to +85C; Temp_Range: -40C to +105C°C; VOLTAGE: 1.1V
U1 = MIMX9122DVXxLAA_BGA208_A: IC CPU SINGLE CORTEX A55 1.4GHz -- FCPBGA208; 3D_Mechanical_Footprint_File: http://fcl.am.freescale.net/ALLEGRO/step/pbga208_0p5_9x9mm_sm.STEP; AGILE_PN: 330-10031; CAD_APPROVED: Yes; HEIGHT: 1mm; MFG_NAME01: NXP SEMICONDUCTOR; Package Size: FCPBGA208; ROHS: NULL; Temp Range: -40  °C to +105 °C
C32 C113 C117 C226 C232 C267 C286 C288 = CAP_NP: CAP CER 0.1UF 25V 10% X5R 0402; AGILE_PN: 150-78633; CAD_APPROVED: Yes; FPLIST: CC0402_25,CC0402_HD,0402_CC,capc0402_l; HEIGHT: 0.55MM; MFG_NAME01: YAGEO AMERICA; MFG_PN01: CC0402KRX5R8BB104; Package Size: 0402; ROHS: Yes; Rated Voltage: 25V; Temp Range: -55C to +85C; Tolerance: 10%; VOLTAGE: 25V
C35 C114 C120 C224 C269 C289 = CAP_NP: CAP CER 1uF 16V 10% X5R 0402; AGILE_PN: 150-78973; CAD_APPROVED: Yes; FPLIST: CC0402_25,CC0402_HD,0402_CC,capc0402_l; HEIGHT: 0.55 MM; MFG_NAME01: TDK; MFG_PN01: C1005X5R1C105K; ROHS: Yes; Rated Voltage: 16V; SIGNAL_MODEL: DEFAULT_CAPACITOR_1e+06pF_2_1; TOL: 10%; Temp Range: -55C to +85C; Tolerance: 10%; VOLTAGE: 16V; voltage rating: 16V
C49 = CAP_NP: CAP CER 0.1UF 25V 10% X5R 0402; AGILE_PN: 150-78633; ASSY_OPT: DNP; CAD_APPROVED: Yes; FPLIST: CC0402_25,CC0402_HD,0402_CC,capc0402_l; HEIGHT: 0.55MM; MFG_NAME01: YAGEO AMERICA; MFG_PN01: CC0402KRX5R8BB104; Package Size: 0402; ROHS: Yes; Rated Voltage: 25V; Temp Range: -55C to +85C; Tolerance: 10%; VOLTAGE: 25V
R61 = RES: RES MF 100K 1/16W 5% 0402; AGILE_PN: 470-75597; CAD_APPROVED: Yes; FPLIST: RC0402_25,RC0402_HD,0402_CC; HEIGHT: 0.40 MM; MFG_NAME01: VENKEL COMPANY; MFG_PN01: CR0402-16W-104JT; ROHS: Yes; Temp Range: -55C to +155C; Temp_Range: -55C to +155C; Tolerance: 5%; VOLTAGE: 50V
R62 R66 R89 R96 R190 = RES: RES MF 100K 1/16W 5% 0402; AGILE_PN: 470-75597; CAD_APPROVED: Yes; FPLIST: RC0402_25,RC0402_HD,0402_CC; HEIGHT: 0.40 MM; MFG_NAME01: VENKEL COMPANY; MFG_PN01: CR0402-16W-104JT; ROHS: Yes; Temp Range: -55C to +155C; Tolerance: 5%; VOLTAGE: 50V
R63 R67 R90 R97 = RES: RES MF 4.7K 1/16W 5% 0402; AGILE_PN: 470-75626; CAD_APPROVED: Yes; FPLIST: RC0402_25,RC0402_HD,0402_CC,RC0402_X2; HEIGHT: 0.41mm; MFG_NAME01: NIC COMPONENTS CORP; MFG_PN01: NRCL04J472TRF; ROHS: Yes; Tolerance: 5%
R68-R75 R95 R99 R101 R116 R119 R123 R131 R137-R144 = RES: RES MF 100 OHM 1/16W 5% 0402; AGILE_PN: 470-82142; CAD_APPROVED: Yes; FPLIST: RC0402_25,RC0402_HD,RC0402_X2,0402_CC; HEIGHT: 0.45MM; MFG_NAME01: SMEC; MFG_PN01: RC73L2Z101JTF; ROHS: Yes; Temp Range: -55°C to +175°C; Tolerance: 5%
R110 = RES: RES MF 15.0K 1/16W 1% 0402; AGILE_PN: 470-76066; CAD_APPROVED: Yes; FPLIST: RC0402_25,RC0402_HD,0402_CC; HEIGHT: 0.4 MM; MFG_NAME01: NIC COMPONENTS CORP; MFG_PN01: NRCL04F1502TRF; ROHS: Yes; Tolerance: 1%
R111 = RES: RES MF 18K 1/16W 1% 0402; AGILE_PN: 470-82139; CAD_APPROVED: Yes; FPLIST: RC0402_25,RC0402_HD,0402_CC; HEIGHT: 0.4MM; MFG_NAME01: NIC COMPONENTS CORP; MFG_PN01: NRCL04F1802TRF; ROHS: Yes; Temp Range: -55°C to +155°C; Tolerance: 1%; VOLTAGE: 50V
R122 R130 R242 R248 = RES: RES MF ZERO OHM 1/16W 5% 0402; AGILE_PN: 470-75394; ASSY_OPT: DNP; CAD_APPROVED: Yes; FPLIST: RC0402_25,RC0402_HD,RC0402_X2,0402_CC; HEIGHT: 0.45; MFG_NAME01: YAGEO AMERICA; MFG_PN01: RC0402JR-070RL; ROHS: Yes; Temp Range: -55 to +155C; Tolerance: 5%; VOLTAGE: 1/16W
R433 R434 = RES: RES MF 2.2K 1/16W 5% 0402; AGILE_PN: 470-76602; ASSY_OPT: DNP; CAD_APPROVED: Yes; FPLIST: RC0402_25,RC0402_HD,0402_CC; HEIGHT: 0.4 MM; MFG_NAME01: YAGEO AMERICA; MFG_PN01: RC0402JR-072K2L; RATING: 1/16W; ROHS: Yes; Tolerance: 5%
SW4 = CHS-04TA_SW: SW SPST SLD WSH 25MA 24V DIP-4 SMT; 3D_Mechanical_Footprint_File: ftp://fcl.am.freescale.net/ALLEGRO/step/sw_chs_04_a.step; AGILE_PN: 510-77691; CAD_APPROVED: Yes; HEIGHT: 2.5MM; MFG_NAME01: NIDEC COPAL ELECTRONICS CORP; ROHS: Yes
U9 U10 U27 U29-U31 = TMUX1574RSVR_A: IC MUX SW SPDT 1.8V UQFN16; 3D_Mechanical_Footprint_File: http://fcl.am.freescale.net/ALLEGRO/step/pqfn16_0p4_2p65x1p85.STEP; AGILE_PN: 312-82341; CAD_APPROVED: Yes; HEIGHT: 0.55; MFG_NAME01: TEXAS INSTRUMENTS; ROHS: Yes; Temp Range: -40C to +125C; VOLTAGE: 1.5-5.5V
U15 = PCAL6524HE_QFN: IC I/O EXPANDER 24-BIT I2C 0.8-3.6V/1.65-5.5V UQFN32; 3D_Mechanical_Footprint_File: http://fcl.am.freescale.net/ALLEGRO/step/uqfn32_0p5_5x5_ep3x3.step; AGILE_PN: 315-81642; CAD_APPROVED: Yes; HEIGHT: 0.6; MFG_NAME01: NXP SEMICONDUCTOR; ROHS: Yes; Temp Range: -40C to +85C; VOLTAGE: 0.8-3.6V/1.65-5.5
C69 C70 = CAP_NP: CAP CER 18pF 50V 5% C0G 0201; AGILE_PN: 150-79476; CAD_APPROVED: Yes; FPLIST: CC0201,CC0201_HD,0201_CC; HEIGHT: 0.33MM; MFG_NAME01: MURATA; MFG_PN01: GRM0335C1H180JA01D; Package Size: 0201; Package Type: &#966;180mm Paper taping; ROHS: Yes; Rated Voltage: 50V; Temp Range: -55C to +125C; Tolerance: 5%; VOLTAGE: 50V
C74 C82 C83 = CAP_NP: CAP CER 22uF 10V 20% X5R 0603; AGILE_PN: 150-79530; ASSY_OPT: DNP; CAD_APPROVED: Yes; FPLIST: CC0603_OV,CC0603,0603_cc_tol; HEIGHT: 1MM; MFG_NAME01: SAMSUNG; MFG_PN01: CL10A226MP7LUNC; Package Size: 0603; ROHS: Yes; Rated Voltage: 10V; SIGNAL_MODEL: DEFAULT_CAPACITOR_2.2e+07pF_2_1; Temp Range: -55C to +85C; Tolerance: 20%; VOLTAGE: 10V; WVDC: 6.3V
C87 C89 C254 = CAP_NP: CAP CER 1uF 16V 10% X5R 0402; AGILE_PN: 150-78973; CAD_APPROVED: Yes; FPLIST: CC0402_25,CC0402_HD,0402_CC,capc0402_l; HEIGHT: 0.55 MM; MFG_NAME01: TDK; MFG_PN01: C1005X5R1C105K; ROHS: Yes; Rated Voltage: 16V; Temp Range: -55C to +85C; Tolerance: 10%; VOLTAGE: 16V; voltage rating: 16V
C88 C91 C92 C257 = CAP_NP: CAP CER 4.7uF 10V 10% X5R 0402; AGILE_PN: 150-80044; CAD_APPROVED: Yes; FPLIST: cc0402_tol0p15,cc0402_tol0p15_ov,0402_cc_nsp; HEIGHT: 0.65MM; MFG_NAME01: SAMSUNG ELECTRO MECHANICS; MFG_PN01: CL05A475KP5NRNC; ROHS: Yes; Rated Voltage: 10V; Temp Range: -55C to +85C; Tolerance: 10%; VOLTAGE: 10V
C90 = CAP_NP: CAP CER 2.2uF 10V 10% X5R 0402; AGILE_PN: 150-78974; CAD_APPROVED: Yes; FPLIST: CC0402_25,CC0402_HD,0402_CC,capc0402_l; HEIGHT: 0.55 MM; MFG_NAME01: TDK; MFG_PN01: C1005X5R1A225K; Package Size: 0402; ROHS: Yes; Rated Voltage: 10V; Temp Range: -55C to +85C; Tolerance: 10%; VOLTAGE: 10V
C239 C241 C242 C246 C248 C253 = CAP_NP: CAP CER 10uF 16V 20% X5R 0603; AGILE_PN: 150-80336; CAD_APPROVED: Yes; FPLIST: CC0603_OV,CC0603,0603_CC,cc0603_0805_nsp; HEIGHT: 1; MFG_NAME01: MURATA; MFG_PN01: GRM188R61C106MA73D; Package Size: 0603; Package Type: SMD; ROHS: Yes; Rated Voltage: 16V; Temp Range: -55C to +85C; Temp_Range: -55°C to +85°C; Tolerance: 20%; VOLTAGE: 16V
C250 = CAP_NP: CAP CER 4.7uF 16V 10% X5R 0603; AGILE_PN: 150-80061; CAD_APPROVED: Yes; FPLIST: CC0603_OV,CC0603,cc0603_0805_nsp,0603_CC_NSP; HEIGHT: 0.95MM; MFG_NAME01: MURATA; MFG_PN01: GRM188R61C475KE11D; ROHS: Yes; Rated Voltage: 16V; Temp Range: -55C to +85C; Tolerance: 10%; VOLTAGE: 16V
D28 = LED: LED RED SGL 25MA 0603; AGILE_PN: 370-76658; CAD_APPROVED: Yes; HEIGHT: 0.8; MFG_NAME01: DIALIGHT; MFG_PN01: 598-8010-107F; ROHS: Yes
L5 L6 L8 L9 = INDUCTOR: IND PWR 0.47uH@1MHz 3.4A 20% 2016; AGILE_PN: 180-78995; CAD_APPROVED: Yes; HEIGHT: 1.2; MFG_NAME01: SHENZHEN SUNLORD ELECTRONICS CO., LTD; MFG_PN01: WPN201612HR47MT; PART_TYPE: INDUCTOR\POWER; Package Size: 2x1.6x1.2 mm; ROHS: Yes; Temp Range: -40°C to 125°C; Temp_Range: -40°C to 125°C; Tolerance: 20%
QZ2 = XTAL: XTAL 32.768KHZ 12.5PF 20PPM 3.2X1.5MM SMT; 3D_Mechanical_Footprint_File: http://fcl.am.freescale.net/ALLEGRO/step/xtal2-3p2x1p5-sm.step; AGILE_PN: 230-77653; CAD_APPROVED: Yes; HEIGHT: 0.9; MFG_NAME01: ABRACON CORPORATION; MFG_PN01: ABS07-32.768KHZ-T; ROHS: Yes
R193 = RES: RES MF 1.0M 1/20W 5% AEC-Q200 0201; AGILE_PN: 470-79975; ASSY_OPT: DNP; CAD_APPROVED: Yes; FPLIST: RC0201,0201_CC; HEIGHT: 0.26MM; MFG_NAME01: PANASONIC; MFG_PN01: ERJ-1GNJ105C; ROHS: Yes; Temp Range: 55°C ~ 125°C; Temp_Range: 55°C ~ 125°C; Tolerance: 5%; VOLTAGE: 25V
R382 = RES: RES MF 1.0K 1/16W 1% 0402; AGILE_PN: 470-76037; CAD_APPROVED: Yes; FPLIST: RC0402_25,RC0402_HD,RC0402_X2,0402_CC; HEIGHT: 0.4MM; MFG_NAME01: VISHAY; MFG_PN01: CRCW04021K00FKEDC; ROHS: Yes; Tolerance: 1%; VOLTAGE: 1/16W
TP59 TP66 TP74 TP76 TP102 TP105 TP111-TP113 = T_POINT_R: TEST POINT PAD .035 SMT, no part to order; AGILE_PN: 510-75618; ASSY_OPT: DNP; CAD_APPROVED: Yes; HEIGHT: 0.1MM; ROHS: Yes
U23 = PF9453AHN_QFN40P: IC POWER MANAGEMENT 2.65-5.5V QFN40; 3D_Mechanical_Footprint_File: http://fcl.am.freescale.net/ALLEGRO/step/qfn40_0p4_5x5_ep146x146.STEP; AGILE_PN: TMP-CIP-18773; CAD_APPROVED: Yes; HEIGHT: 1mm; MFG_NAME01: NXP SEMICONDUCTOR; PRE_APN: 315-10338; ROHS: NULL; Temp Range: -40 °C  to  +105°C
U34 = 74AUP1G07GW: IC LOGIC GATE BUFFER 0.8-3.6V TSSOP5; 3D_Mechanical_Footprint_File: http://fcl.am.freescale.net/ALLEGRO/step/sc70-5.STEP; AGILE_PN: 312-81232; CAD_APPROVED: Yes; HEIGHT: 1.1; MFG_NAME01: NEXPERIA; MFG_PN01: 74AUP1G07GW,125; ROHS: Yes; VOLTAGE: 0.8-3.6V

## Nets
AGND: C254.1 R439.2 U23.34(AGND)
GND: C32.2 C35.2 C49.2 C69.2 C70.2 C73.2 C74.2 C75.2 C76.2 C80.2 C81.2 C82.2 C83.2 C84.2 C87.1 C88.2 C89.2 C90.2 C91.2 C92.2 C101.2 C102.2 C104.2 C105.2 C106.2 C107.2 C108.2 C109.2 C110.2 C111.2 C113.2 C114.2 C115.2 C116.2 C117.2 C118.2 C119.2 C120.2 C129.2 C130.2 C131.2 C132.2 C133.2 C136.2 C137.2 C138.2 C139.2 C140.2 C144.2 C145.2 C146.2 C151.2 C152.2 C153.2 C155.2 C201.2 C202.2 C203.2 C204.2 C205.2 C206.2 C207.2 C208.2 C209.2 C210.2 C211.2 C212.2 C213.2 C214.2 C215.2 C216.2 C217.2 C218.2 C219.2 C220.2 C221.2 C222.2 C224.2 C226.2 C232.2 C239.1 C241.1 C242.1 C246.1 C248.1 C250.2 C253.2 C257.2 C267.2 C269.2 C286.2 C288.2 C289.2 D28.C(CATHODE) GND3.1(Pin1) GND5.1(Pin1) GND8.1(Pin1) GND9.1(Pin1) GND10.1(Pin1) GND28.1(Pin1) R39.2 R61.2 R62.2 R66.2 R89.2 R96.2 R111.2 R201.2 R204.2 R207.1 R208.1 R265.2 R266.2 R404.2 R439.1 R442.2 U1.A1(VSS1) U1.A17(VSS39) U1.C6(VSS10) U1.C8(VSS17) U1.C12(VSS26) U1.C14(VSS33) U1.D3(VSS3) U1.D15(VSS34) U1.E12(VSS27) U1.F3(VSS4) U1.F6(VSS11) U1.F8(VSS18) U1.F10(VSS23) U1.F15(VSS35) U1.G6(VSS12) U1.G12(VSS28) U1.H3(VSS5) U1.H9(VSS21) U1.H15(VSS36) U1.J6(VSS13) U1.J12(VSS29) U1.K3(VSS6) U1.K9(VSS22) U1.L7(VSS14) U1.M3(VSS7) U1.M6(VSS15) U1.M8(VSS19) U1.M10(VSS24) U1.M12(VSS31) U1.M15(VSS37) U1.N10(VSS30) U1.P3(VSS8) U1.P15(VSS38) U1.R4(VSS9) U1.R6(VSS16) U1.R8(VSS20) U1.R10(VSS40) U1.R12(VSS32) U1.R14(VSS41) U1.U1(VSS2) U1.U17(VSS25) U2.A3(VSS1) U2.A10(VSS2) U2.AB3(VSS55) U2.AB5(VSS56) U2.AB8(VSS57) U2.AB10(VSS58) U2.C1(VSS3) U2.C5(VSS4) U2.C8(VSS5) U2.C12(VSS6) U2.D2(VSS7) U2.D4(VSS8) U2.D9(VSS9) U2.D11(VSS10) U2.E1(VSS11) U2.E5(VSS12) U2.E8(VSS13) U2.E12(VSS14) U2.G1(VSS15) U2.G3(VSS16) U2.G5(VSS17) U2.G8(VSS18) U2.G10(VSS19) U2.G12(VSS20) U2.J1(VSS21) U2.J3(VSS22) U2.J10(VSS23) U2.J12(VSS24) U2.K2(VSS25) U2.K4(VSS26) U2.K9(VSS27) U2.K11(VSS28) U2.N2(VSS29) U2.N4(VSS30) U2.N9(VSS31) U2.N11(VSS32) U2.P1(VSS33) U2.P3(VSS34) U2.P10(VSS35) U2.P12(VSS36) U2.T1(VSS37) U2.T3(VSS38) U2.T5(VSS39) U2.T8(VSS40) U2.T10(VSS41) U2.T12(VSS42) U2.V1(VSS43) U2.V5(VSS44) U2.V8(VSS45) U2.V12(VSS46) U2.W2(VSS47) U2.W4(VSS48) U2.W9(VSS49) U2.W11(VSS50) U2.Y1(VSS51) U2.Y5(VSS52) U2.Y8(VSS53) U2.Y12(VSS54) U9.6(GND) U10.6(GND) U15.25(VSS) U15.26(ADDR) U15.33(EXPAD) U23.41(EPAD) U27.6(GND) U29.6(GND) U30.6(GND) U31.6(GND) U34.3(GND) ; also on sheet 1 2 3 7 8 9 10 11 12 20 21 22 23 24
VCC_ANA_1V8: C80.1 C144.1 C145.1 C146.1 L7.2 U1.E6(VDD_USB_1P8) U1.F12(VDD_ANA0_1P8) U1.L12(VDD_ANAVDET_1P8) U1.N8(VDD_ANA1_1P8)
VDD_1P8: C83.1 C84.1 L9.2 TP105.1(TP) U23.29(BUCK3FB) ; also on sheet 2
VDD_1V8: C286.1 U34.5(VCC) ; also on sheet 2 7 10 11 22 23 24
VDD_3P3: C75.1 C76.1 L6.2 TP76.1(TP) U23.21(BUCK4FB) ; also on sheet 2
VDD_3V3: C32.1 C35.1 C87.2 C113.1 C114.1 C117.1 C120.1 C224.1 C226.1 C232.1 C267.1 C269.1 C288.1 C289.1 R63.2 R67.2 R90.2 R97.2 R117.1 R256.1 R382.1 R430.1 R433.1 R434.1 R467.1 U9.14(VDD) U10.14(VDD) U15.27(VDD_P) U15.31(VDD_I2C) U23.32(LSWIN) U27.14(VDD) U29.14(VDD) U30.14(VDD) U31.14(VDD) ; also on sheet 1 2 7 8 9 10 11 12 20 21 22 23 24
VDD_ANA_0P8: C92.1 TP113.1(TP) U23.1(LDO2) ; also on sheet 2
VDD_ANA_0V8: C130.1 C131.1 C132.1 C133.1 U1.C4(VDD_USB_0P8) U1.F13(VDD_ANA0_0P8) U1.M13(VDD_ANA1_0P8) ; also on sheet 2
VDD_ANA_1V8: L7.1 ; also on sheet 2
VDD_SNVS_0V8: C102.1 U1.C10(VDD_BBSM_0P8_CAP)
VDD_SOC: C104.1 C105.1 C106.1 C107.1 C108.1 C109.1 C110.1 C111.1 R242.2 U1.G7(VDD_SOC1) U1.G9(VDD_SOC4) U1.G11(VDD_SOC5) U1.H7(VDD_SOC2) U1.H11(VDD_SOC6) U1.K7(VDD_SOC3) U1.K11(VDD_SOC7) ; also on sheet 2
VDD_SOC_0V85: C81.1 C82.1 L8.2 R235.1 TP102.1(TP) ; also on sheet 2
VDD_USB_3V3: C155.1 U1.E8(VDD_USB_3P3) ; also on sheet 2
VINT: C89.1 U23.36(VINT)
AUD_nMUTE: R139.2 ; also on sheet 9
BUF_POR: R118.1 R256.2 U34.4(Y)
CAN1_RX: U10.1(S1B) ; also on sheet 21
CAN1_TX: U10.8(S3B) ; also on sheet 21
CAN_STBY: U10.4(S2B) ; also on sheet 21
DMIC_PDM_CLK: U10.9(S3A) ; also on sheet 8
DMIC_PDM_DATA0: U10.16(S1A) ; also on sheet 8
DMIC_PDM_DATA1: U10.3(S2A) ; also on sheet 8
DRAM_CA0_A: TP36.1(Pin1) U1.F1(DRAM_CA0_A) U2.H2(CA0)
DRAM_CA1_A: U1.E2(DRAM_CA1_A) U2.J2(CA1)
DRAM_CA2_A: U1.D2(DRAM_CA2_A) U2.H9(CA2)
DRAM_CA3_A: U1.C1(DRAM_CA3_A) U2.H10(CA3)
DRAM_CA4_A: U1.B2(DRAM_CA4_A) U2.H11(CA4)
DRAM_CA5_A: U1.A2(DRAM_CA5_A) U2.J11(CA5)
DRAM_CK_C_A: R205.2 U1.B1(DRAM_CK_C_A) U2.J9(CK_c)
DRAM_CK_T_A: R205.1 U1.C2(DRAM_CK_T_A) U2.J8(CK_t)
DRAM_CKE0_A: R207.2 U1.G1(DRAM_CKE0_A) U2.J4(CKE)
DRAM_CKE1_A: R208.2 U1.F2(DRAM_CKE1_A) U2.J5(NC4)
DRAM_DATA0_A: TP60.1(Pin1) U1.L2(DRAM_DQ00_A) U2.F4(DQ4)
DRAM_DATA1_A: TP54.1(Pin1) U1.L1(DRAM_DQ01_A) U2.E4(DQ5)
DRAM_DATA2_A: TP51.1(Pin1) U1.K2(DRAM_DQ02_A) U2.C4(DQ6)
DRAM_DATA3_A: TP49.1(Pin1) U1.K1(DRAM_DQ03_A) U2.B4(DQ7)
DRAM_DATA4_A: TP47.1(Pin1) U1.J1(DRAM_DQ04_A) U2.B2(DQ0)
DRAM_DATA5_A: TP45.1(Pin1) U1.H2(DRAM_DQ05_A) U2.C2(DQ1)
DRAM_DATA6_A: TP39.1(Pin1) U1.H1(DRAM_DQ06_A) U2.E2(DQ2)
DRAM_DATA7_A: TP43.1(Pin1) U1.G2(DRAM_DQ07_A) U2.F2(DQ3)
DRAM_DATA8_A: TP78.1(Pin1) U1.T2(DRAM_DQ08_A) U2.E11(DQ10)
DRAM_DATA9_A: TP79.1(Pin1) U1.U2(DRAM_DQ09_A) U2.F11(DQ11)
DRAM_DATA10_A: TP77.1(Pin1) U1.T1(DRAM_DQ10_A) U2.C11(DQ9)
DRAM_DATA11_A: TP73.1(Pin1) U1.R2(DRAM_DQ11_A) U2.B11(DQ8)
DRAM_DATA12_A: TP67.1(Pin1) U1.N1(DRAM_DQ12_A) U2.C9(DQ14)
DRAM_DATA13_A: TP72.1(Pin1) U1.N2(DRAM_DQ13_A) U2.B9(DQ15)
DRAM_DATA14_A: TP65.1(Pin1) U1.M2(DRAM_DQ14_A) U2.E9(DQ13)
DRAM_DATA15_A: TP64.1(Pin1) U1.M1(DRAM_DQ15_A) U2.F9(DQ12)
DRAM_DMI0_A: TP48.1(Pin1) U1.J2(DRAM_DMI0_A) U2.C3(DMI0)
DRAM_DMI1_A: U1.R1(DRAM_DMI1_A) U2.C10(DMI1)
DRAM_nCS0_A: TP35.1(Pin1) U1.D1(DRAM_CS0_A) U2.H4(CS)
DRAM_nCS1_A: U1.E1(DRAM_CS1_A) U2.H3(NC3)
DRAM_nRESET: R102.1 R201.1 U1.F4(DRAM_RESET_N) U2.T11(RESET_n)
DRAM_SDQS0_C_A: U1.K4(DRAM_DQS0_C_A) U2.E3(DQS0_c)
DRAM_SDQS0_T_A: U1.M4(DRAM_DQS0_T_A) U2.D3(DQS0_t)
DRAM_SDQS1_C_A: U1.P2(DRAM_DQS1_C_A) U2.E10(DQS1_c)
DRAM_SDQS1_T_A: U1.P1(DRAM_DQS1_T_A) U2.D10(DQS1_t)
DRAM_ZN: R204.1 U1.H4(DRAM_ZQ)
DRAM_ZQ0: R209.2 U2.A5(ZQ)
DRAM_ZQ1: R211.1 U2.A8(NC1)
ENET1_nRST: R95.2 ; also on sheet 10
EXP3V3_EN: R70.2 ; also on sheet 23
EXP5V_EN: R141.2 ; also on sheet 23
EXP_GPIO_IO08: U9.3(S2A) ; also on sheet 23
EXP_GPIO_IO09: U9.9(S3A) ; also on sheet 23
EXP_GPIO_IO10: U9.12(S4A) ; also on sheet 23
EXP_GPIO_IO11: U9.16(S1A) ; also on sheet 23
EXP_nIRQ: R135.1 ; also on sheet 3
EXP_SEL: R61.1 R69.2 U9.15(SEL)
EXT1_PWREN: R101.2 ; also on sheet 22
GPIO_IO08: U9.5(D2) ; also on sheet 20
GPIO_IO09: U9.7(D3) ; also on sheet 20
GPIO_IO10: U9.10(D4) ; also on sheet 20
GPIO_IO11: U9.2(D1) ; also on sheet 20
I2C1_SCL: R122.1 ; also on sheet 12 20 22
I2C1_SDA: R130.1 ; also on sheet 12 20 22
I2C2_SCL: R121.1 R169.1 ; also on sheet 20
I2C2_SDA: R129.1 R168.1 ; also on sheet 20
IOEXP_IO24: R144.2 ; also on sheet 23
IOEXP_IO25: R143.2 ; also on sheet 23
IOEXP_IO27: R131.2 ; also on sheet 23
JTAG_TCK: U27.2(D1) ; also on sheet 3
JTAG_TDI: U27.5(D2) ; also on sheet 3
JTAG_TDO: U27.10(D4) ; also on sheet 3
JTAG_TMS: U27.7(D3) ; also on sheet 3
JTG_TCK: U27.1(S1B) ; also on sheet 7
JTG_TDI: U27.4(S2B) ; also on sheet 7
JTG_TDO: U27.11(S4B) ; also on sheet 7
JTG_TMS: U27.8(S3B) ; also on sheet 7
LPD4_VDD1: C201.1 C202.1 C203.1 C204.1 C205.1 C209.1 U2.F1(VDD1_1) U2.F12(VDD1_2) U2.G4(VDD1_3) U2.G9(VDD1_4) U2.T4(VDD1_5) U2.T9(VDD1_6) U2.U1(VDD1_7) U2.U12(VDD1_8) ; also on sheet 2
LPD4_VDD2: C136.1 C137.1 C138.1 C139.1 C140.1 C151.1 C152.1 C153.1 C206.1 C207.1 C208.1 C210.1 C211.1 C212.1 C213.1 C214.1 C215.1 C216.1 C217.1 C218.1 C219.1 C220.1 C221.1 C222.1 R209.1 R210.1 R211.2 U1.F5(VDD2_DDR_5) U1.H5(VDD2_DDR_6) U1.K5(VDD2_DDR_2) U1.M5(VDD2_DDR_3) U1.N6(VDD2_DDR_4) U1.P4(VDD2_DDR_1) U2.A4(VDD2_1) U2.A9(VDD2_2) U2.AA3(VDDQ17) U2.AA5(VDDQ18) U2.AA8(VDDQ19) U2.AA10(VDDQ20) U2.AB4(VDD2_23) U2.AB9(VDD2_24) U2.B3(VDDQ1) U2.B5(VDDQ2) U2.B8(VDDQ3) U2.B10(VDDQ4) U2.D1(VDDQ5) U2.D5(VDDQ6) U2.D8(VDDQ7) U2.D12(VDDQ8) U2.F3(VDDQ9) U2.F5(VDD2_3) U2.F8(VDD2_4) U2.F10(VDDQ10) U2.H1(VDD2_5) U2.H5(VDD2_6) U2.H8(VDD2_7) U2.H12(VDD2_8) U2.K1(VDD2_9) U2.K3(VDD2_10) U2.K10(VDD2_11) U2.K12(VDD2_12) U2.N1(VDD2_13) U2.N3(VDD2_14) U2.N10(VDD2_15) U2.N12(VDD2_16) U2.R1(VDD2_17) U2.R5(VDD2_18) U2.R8(VDD2_19) U2.R12(VDD2_20) U2.U3(VDDQ11) U2.U5(VDD2_21) U2.U8(VDD2_22) U2.U10(VDDQ12) U2.W1(VDDQ13) U2.W5(VDDQ14) U2.W8(VDDQ15) U2.W12(VDDQ16) ; also on sheet 2
LPD4_VDD2_1V1: C73.1 C74.1 L5.2 TP74.1(TP) U23.10(BUCK1FB) ; also on sheet 2
LX1: L5.1 U23.8(LX1_1) U23.9(LX1_2)
LX2: L8.1 U23.4(LX2_1) U23.5(LX2_2)
LX3: L9.1 U23.27(LX3_1) U23.28(LX3_2)
LX4: L6.1 U23.22(LX4_1) U23.23(LX4_2)
M2_nALERT: R119.2 ; also on sheet 22
M2_nDIS1: R71.2 ; also on sheet 22
M2_nDIS2: R72.2 ; also on sheet 22
M2_SAI1_RXD0: U31.11(S4B) ; also on sheet 22
M2_SAI1_TXC: U31.4(S2B) ; also on sheet 22
M2_SAI1_TXD0: U31.8(S3B) ; also on sheet 22
M2_SAI1_TXFS: U31.1(S1B) ; also on sheet 22
M2_SD_CLK: U29.16(S1A) ; also on sheet 22
M2_SD_CMD: U29.3(S2A) ; also on sheet 22
M2_SD_DATA0: U30.9(S3A) ; also on sheet 22
M2_SD_DATA1: U30.12(S4A) ; also on sheet 22
M2_SD_DATA2: U30.16(S1A) ; also on sheet 22
M2_SD_DATA3: U30.3(S2A) ; also on sheet 22
M2_UART_nWAKE: R140.2 ; also on sheet 22
MIC/CAN_SEL: R74.2 R89.1 SW4.5 U10.15(SEL)
NVCC_1V8: C115.1 C116.1 U1.L6(NVCC_WAKEUP_1) U1.L9(NVCC_WAKEUP_2) U1.L11(NVCC_WAKEUP_3) ; also on sheet 2
NVCC_3V3: C118.1 C119.1 U1.H13(NVCC_AON) U1.K13(NVCC_GPIO) ; also on sheet 2
NVCC_BBSM_1P8: C90.1 R190.1 TP111.1(TP) U23.38(LDO_SNVS) ; also on sheet 2
NVCC_BBSM_1V8: C101.1 U1.E10(NVCC_BBSM_1P8) ; also on sheet 2 3 23
NVCC_SD: C91.1 C257.1 TP112.1(TP) U23.39(LDO1) ; also on sheet 2
NVCC_SD2: C129.1 U1.N12(NVCC_SD2) ; also on sheet 2 20 24
ODT_CA_A: R210.2 U2.G2(ODT_CA)
PDM_CLK: U10.7(D3) ; also on sheet 20
PDM_DATA0: U10.2(D1) ; also on sheet 20
PDM_DATA1: U10.5(D2) ; also on sheet 20
PMIC_32K_OUT: U23.14(CLK_32K_OUT) ; also on sheet 22
PMIC_nINT: R116.2 R117.2 U23.19(IRQ_B)
PMIC_ON_REQ: R191.1 ; also on sheet 3 7 12
PMIC_STBY_REQ: R237.1 ; also on sheet 3 7
POR_B: U23.11(POR_B) U34.2(A) ; also on sheet 3 7
QSPIA_DATA0: U30.8(S3B) ; also on sheet 24
QSPIA_DATA1: U30.11(S4B) ; also on sheet 24
QSPIA_DATA2: U30.1(S1B) ; also on sheet 24
QSPIA_DATA3: U30.4(S2B) ; also on sheet 24
QSPIA_nSS0: U29.4(S2B) ; also on sheet 24
QSPIA_SCLK: U29.1(S1B) ; also on sheet 24
RTC_nINTA: R138.2 ; also on sheet 21
SAI1_DAC_MCLK: U31.12(S4A) ; also on sheet 9
SAI1_DAC_TXC: U31.3(S2A) ; also on sheet 9
SAI1_DAC_TXD: U31.9(S3A) ; also on sheet 9
SAI1_DAC_TXFS: U31.16(S1A) ; also on sheet 9
SAI1_EN_B: R123.2 R465.1
SAI1_RXD0: U31.10(D4) ; also on sheet 20
SAI1_SEL: R66.1 R73.2 SW4.3 U31.15(SEL)
SAI1_TXC: U31.5(D2) ; also on sheet 20
SAI1_TXD0: U31.7(D3) ; also on sheet 1 20
SAI1_TXFS: U31.2(D1) ; also on sheet 1 20
SAI3_EN_B: R68.2 ; also on sheet 23
SAI3_TX/RX_SEL: R99.2 ; also on sheet 23
SD2_nRST: R236.1 ; also on sheet 20
SD2_VSEL: U23.35(SD_VSEL) ; also on sheet 20
SD3_CLK: U29.2(D1) ; also on sheet 20
SD3_CMD: U29.5(D2) ; also on sheet 20
SD3_DATA0: U30.7(D3) ; also on sheet 20
SD3_DATA1: U30.10(D4) ; also on sheet 20
SD3_DATA2: U30.2(D1) ; also on sheet 20
SD3_DATA3: U30.5(D2) ; also on sheet 20
SD3_nRST: R110.2 R111.1 ; also on sheet 22
SD3_nWAKE: R142.2 ; also on sheet 22
SD3_QSPI_SEL: R62.1 R75.2 R248.1 SW4.1 U29.15(SEL) U30.15(SEL)
SPI3_CLK: U9.1(S1B) ; also on sheet 22
SPI3_CS0: U9.4(S2B) ; also on sheet 22
SPI3_MISO: U9.8(S3B) ; also on sheet 22
SPI3_MOSI: U9.11(S4B) ; also on sheet 22
SYS_nRST: R189.1 TP66.1(TP) ; also on sheet 7 23
TCPC1_nINT: R136.1 ; also on sheet 11
TCPC_nINT: R137.2 ; also on sheet 12
UART5/JTAG_SEL: R96.1 R248.2 SW4.7 U27.15(SEL)
UART5_CTSI: U27.16(S1A) ; also on sheet 22
UART5_RTSO: U27.9(S3A) ; also on sheet 22
UART5_RXD: U27.3(S2A) ; also on sheet 22
UART5_TXD: U27.12(S4A) ; also on sheet 22
VSD_3V3: C88.1 U23.33(LSWOUT/DBUS_IN) ; also on sheet 24
VSYS: C254.2 R481.2 U23.37(VSYS)
VSYS_5V: C239.2 C241.2 C242.2 C246.2 C248.2 C250.1 C253.1 R481.1 U23.2(INL2) U23.6(INB12_1) U23.7(INB12_2) U23.24(INB34_1) U23.25(INB34_2) U23.26(INB34_3) U23.40(INL1) ; also on sheet 2
WDOG_B: R188.1 TP59.1(TP) ; also on sheet 7 20
XIN_32K: C70.1 QZ2.2 R193.1 U23.16(XTAL_IN)
XOUT_32K: C69.1 QZ2.1 R193.2 U23.17(XTAL_OUT)
N117395484: R189.2 R190.2 U23.18(PMIC_RST_B)
N117395690: R188.2 U23.20(WDOG_B)
N117395722: R191.2 U23.15(PMIC_ON_REQ)
N117395724: R235.2 R242.1 U23.3(BUCK2FB)
N117395763: R237.2 U23.31(PMIC_STBY_REQ)
N117395797: R169.2 U23.12(SCL)
N117395822: R168.2 U23.13(SDA)
N117396699: D28.A(ANODE) R382.2
N117424543: R102.2 U2.G11(NC2)
N117439420: R129.2 R130.2 R434.2 U15.30(SDA)
N117439422: R121.2 R122.2 R433.2 U15.29(SCL)
N117439424: C49.1 R118.2 R430.2 U15.28(~{RESET})
N117439483: R137.1 U15.1(P0_0)
N117439503: R138.1 U15.2(P0_1)
N117439523: R139.1 U15.3(P0_2)
N117439558: R140.1 U15.4(P0_3)
N117439590: R141.1 U15.5(P0_4)
N117439655: R142.1 U15.6(P0_5)
N117439684: R63.1 SW4.2
N117439704: R135.2 R136.2 U15.32(~{INT})
N117439710: R143.1 U15.7(P0_6)
N117439737: R67.1 SW4.4
N117439768: R144.1 U15.8(P0_7)
N117439790: R90.1 SW4.6
N117439833: R97.1 SW4.8
N117439837: R131.1 U15.9(P1_0)
N117439852: R123.1 U15.10(P1_1)
N117439873: R119.1 U15.11(P1_2)
N117439950: R116.1 U15.12(P1_3)
N117439995: R110.1 U15.13(P1_4)
N117440027: R101.1 U15.14(P1_5)
N117440047: R99.1 U15.15(P1_6)
N117440102: R95.1 U15.16(P1_7)
N117440157: R75.1 U15.17(P2_0)
N117440173: R74.1 U15.18(P2_1)
N117440199: R73.1 U15.19(P2_2)
N117440226: R72.1 U15.20(P2_3)
N117440257: R71.1 U15.21(P2_4)
N117440277: R70.1 U15.22(P2_5)
N117440294: R69.1 U15.23(P2_6)
N117440315: R68.1 U15.24(P2_7)
N117440815: R266.1 U30.13(EN)
N117440819: R265.1 U29.13(EN)
N117440823: R404.1 U9.13(EN)
N117441408: R465.2 R467.2 U31.13(EN)
N117441414: R39.1 U10.13(EN)
N117441435: R442.1 U27.13(EN)
N118712568: R236.2 U23.30(LSW_EN/DBUS_OUT)

Not connected (* = marked no-connect by the designer): U2 A1(DNU1)* A2(DNU2)* A11(DNU3)* A12(DNU4)* AA1(DNU7)* AA2(NC40)* AA4(NC41)* AA9(NC42)* AA11(NC43)* AA12(DNU8)* AB1(DNU9)* AB2(DNU10)* AB11(DNU11)* AB12(DNU12)* B1(DNU5)* B12(DNU6)* K5(NC5)* K8(NC6)* N5(NC7)* N8(NC8)* P2(NC9)* P4(NC10)* P5(NC11)* P8(NC12)* P9(NC13)* P11(NC14)* R2(NC15)* R3(NC16)* R4(NC17)* R9(NC18)* R10(NC19)* R11(NC20)* T2(NC21)* U2(NC22)* U4(NC23)* U9(NC24)* U11(NC25)* V2(NC26)* V3(NC27)* V4(NC28)* V9(NC29)* V10(NC30)* V11(NC31)* W3(NC32)* W10(NC33)* Y2(NC34)* Y3(NC35)* Y4(NC36)* Y9(NC37)* Y10(NC38)* Y11(NC39)*; U10 10(D4)* 11(S4B)* 12(S4A)*; U29 7(D3)* 8(S3B)* 9(S3A)* 10(D4)* 11(S4B)* 12(S4A)*; U34 1(NC)*

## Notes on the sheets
sheet 13
- IO MUX / EXP
- I2C IO EXP
- Function Switch
- #PU RES for IRQ
- Switch Setting Table
- #OD, PU MX93
- 1
- Signal
- Setting
- Description
- 2
- 3
- SD3_QSPI_SEL
- 0
- Defalut Low, SDIO for M.2
- 4
- SW4 [1]
- 1
- High, QSPI Flash
- #Share IRQ due to TCPC level trigger rather edge trigger
- #1MHz I2C I/F for IRQ fast response!!!
- SAI1_SEL
- 0
- Defalut Low, SAI1 for Audio DAC
- SW4 [2]
- 1
- High, SAI1 for M.2 Bluetooth
- 1 MHz I2C (Fm+)
- 1.8V
- MIC/CAN_SEL
- 0
- Defalut Low, PDM MIC
- SW4 [3]
- 1
- High, CAN1
- UART5/JTAG_SEL
- 0
- Defalut Low, UART5 for M.2 Bluetooth
- SW4 [4]
- 1
- High, JTAG debug
- #I2C ADDR: 0b'0100010x
- M2 SDIO/QSPI Switch
- SHARED GPIO MUX
- M2 SDIO
- M2 SDIO
- IO EXP
- QSPI
- QSPI
- M.2 802.15.4
- SEL=H:   Dx->SxB
- SEL=H:   Dx->SxB
- SEL=H:   Dx->SxB
- SEL=L:   Dx->SxA
- SEL=L:   Dx->SxA
- SEL=L:   Dx->SxA
- AUDIO DAC/M2 Bluetooth Switch
- PDM MIC/CAN Switch
- M2 UART/JTAG Switch
- AUDIO DAC
- PDM MIC
- M2 UART
- SEL=H:   Dx->SxB
- SEL=L:   Dx->SxA
- M2 I2S/PCM
- CAN1
- JTAG
- SEL=H:   Dx->SxB
- SEL=L:   Dx->SxA
- EN=H:   Disable
- EN=L:   Enable
- Disable the connection as default, make sure SAI(BOOT_MODE)
  signals are not impacted by peripherals before and after POR_B.
sheet 14
- MCIMX91 9x9 package Quick Start Board
- IMX91LP4QSB-09
- Table of Content
- Revision History
- Page 1
- Cover
- Rev. Code
- Date
- By
- Description
- Page 2
- Block Diagram
- A
- 2024-01-12
- NXF91318
- Initial version
- Page 3
- PWR TREE
- A1
- 2024-08-23
- NXF91318
- 1. Change C102 from 0.22uF to 1uF for better noise suppression.
- 2. Change U2 LPDDR4 to NANYA NT6AN512M16AV-J1I, as the old part will be EOL soon.
- Page 4
- CPU PWR
- 3. Change D18, D19 to BAT54HT1 for lower reverse current to reduce power leakage from VLS_3V3 to DCDC_5V.
- 4. Change U36 to MCP6546 to reduce power leakage from comparator input to power supply VDD_5V.
- Page 5
- LPDDR4
- 5. Change R299 from 249K to 226K to decrease the threshold of comparator input for VBUS detect.
- 6. Change C154 to 100uF, C200 to 47uF to improve the transient response of SYS_5V, when load switch U58 is enabled.
- Page 6
- CPU IO/PHY
- 7. DNP R331 to avoid voltage conflict of CCM_CLKO1 between internal pull-up VDD_1V8 and external pull-up VDD_3V3.
- Page 7
- CPU MISC
- 8. Update U23 PF9453AHN symbol.
- A2
- 2024-08-26
- NXF91318
- 1. Update Title Block with new NXP logo.
- Page 8
- eMMC/MicroSD/QSPI
- A3
- 2025-04-16
- NXF91318
- 1. Update U1 part number from MIMX9111CVXXJAA to MIMX9111CVXXJAB.
- Page 9
- IO MUX
- 2. Update U23 part number from PF9453AHN to MPF9453AVMA1HN.
- 3. Update U23 BUCK2 output current from 2A to 2.7A.
- Page 10
- PMIC
- Page 11
- Power Measurement
- Page 12
- SYS PWR
- Page 13
- USB1 TYPE-C
- Page 14
- ENET1
- Page 15
- M.2 WIFI/BT
- Page 16
- IO EXPI/MISC
- Page 17
- CAN/EXT RTC
- Page 18
- AUDIO DAC
- Page 19
- PDM MIC
- Page 20
- REMOTE DEBUG
- Page 21
- BOOT MODE
- Page 22
- Power Measurement Diagram
- Page 23
- I2C Table
- Page 24
- IOMUX
- Preliminary - Subject to Change without Notice!
- This board was designed for maximum flexibility in
  software  development and demonstrates multiple
  functions possible with i.MX processors. Although best
  design practices have been applied, some areas may
  not be suitable for a mass-production design.
sheet 15
- i.MX 91 9x9 QSB BLOCK DIAGRAM
- SYS PWR
- PMIC
- DAC
- Line OUT
- USB C
     PD
- PWR
- Cirrus Logic
    WM8524
- NXP PF9453
- I2C2
- SAI1
- DRAM
- x16 bits
- M.2 NGFF
- LPDDR4
- UART5
- Curr Sense
- LPDDR4: 1GB <x16b>
- M.2
- KEY-E:WiFi/BT...
- PAC1934
- x4 bits
- # NXP Wi-Fi/BT 1x1 WiFi 6 (802.11ax)
- eMMC 5.1
- x8 bits
- SDHC3
- QSPI Nand
- FTDI  FT4232
- SDHC1
- 16GB HS400
- GD  GD5F2GM7RE
- CONNECTIVITY
- MicroSD
- x4 bits
- USB 2.0
- MicroSD
- MicroSD
- SDHC2
- USB 2.0 DRP
- USB C
- i.MX91
- USB1
- SD3.0
- TYPE-C connector
- RTC
- Giga ENET
- I2C1
- ARM:  CORTEX-A55 (1.4GHz)
  9x9 Package
- ENET1
- RGMII
- Realtek RTL8211
- RJ45
- NXP PCF2131
- # AVB, 1588, and IEEE 802.3az
- TEMP
- UART-USB
- CORTEX-A55  DEBUG
- I3C/I2C1
- UART1
- USB C
- FTDI  FT4232
- NXP P3T1085
- Power Measure and Remote Debug Support
- ADC
- CAN
- CAN
- HDR
- ADC
- 2CH x12 bit
- NXP TJA1051T/3
- WTB CN
- PDM
- AUX I2C
- PDM
- PDM MIC ON BOARD
- HDR
- I2C1
- I2C/GPIO
- IO Expander
- I2C2
- NXP  PCAL6524
- PDM MIC
- PDM MIC
- PDM MIC
- PDM MIC
- JTAG/SWD
- UART/I2C/SPI/PDM/ISI...
- JTAG/SWD
- EXP CN
- DEBUG
- UART/I2C/SPI/PDM/ISI...
- # Audio HAT/ RFID/PDM/Camera/LCD...
- HDR
- HDR
sheet 16
- i.MX 91 9x9 QSB PWR TREE
- PMIC
- PMIC: PF9453 CFG
- PF9453
- SEQ
- Tstep
- REGULATOR
- VOL (V)
- MAX I (mA)
- PWR RAIL
- RANGE(V)
- Req I (mA)
- NVCC_BBSM_1P8
- LDO_SNVS
- NVCC_BBSM_1V8
- i.MX91
- 0
- LDO_SNVS
- 1.8
- 10
- NVCC_BBSM_1P8
- 1.65-1.8-1.95
- 2
- VDD_SOC
- 0.61-0.65-0.69
- BUCK2
- VDD_SOC
- 1
- T1
- BUCK2
- 0.85
- 2700
- VDD_SOC
- 0.76-0.8-0.84
- 1500
- 0.8-0.85-0.9
- VDD_USB_0P8
- VDD_ANA_0P8
- USB C SNK PD
- VDD_ANA_0P8
- VDD1 must be powered before VDD2.
- LDO2
- VDD_ANA_0P8
  VDD_USB_0P8
- LPDDR4
- 2
- T2
- LDO2
- 0.8
- 200
- 0.76-0.8-0.9
- 200
- VBUS_IN
- NVCC_WAKEUP
- VDD_USB_1P8
- VDD_ANAx_1P8
- USB C
     PD
- DCDC BUCK
- VDD_1V8
- BUCK3
- VDD1 <1.8V>
- VDD_ANAx_1P8
  NVCC_WAKEUP
  VDD_USB_1P8
  DDR_VDD1
  VDD_1V8
- 5-20V
- R1273L
- VDD2_DDR
- VDD_DDR_1V1
- 3
- T3
- BUCK3
- 1.8
- 2000
- 1.71-1.8-1.89
- 2000
- BUCK1
- VDD2/VDDQ <1.1V>
- VDD_USB_3P3
- NVCC_GPIO
- NVCC_AON
- BUCK4
- VDD_3V3
- eMMC(SD1)
- 4
- T4
- BUCK1
- 1.1
- 2000
- VDD2_DDR/LPD4_VDD2
- 1.06-1.1-1.14
- 1000
- NVCC_SD2
- NVCC_SD2
- 3.3/1.8V
- LDO1
- VCC <3.3V>
- NVCC_AON
  NVCC_GPIO
  VDD_USB_3P3
  VDD_3V3
- VCCQ <1.8V>
- 5
- T5
- BUCK4
- 3.3
- 2500
- 3.0-3.3-3.45
- 2500
- VSD_3V3
- LSW
- QSPI NAND
- 6
- T5
- Load Switch
- 3.3
- 400
- VSD_3V3
- 3.3
- 400
- VCC <1.8V>
- 7
- T6
- LDO1
- 3.3/1.8
- 250
- NVCC_SD2
- 3.3/1.8
- 150
- 8
- Tpor_b
- POR_B
- --
- --
- POR_B
- --
- --
- MicroSD(SD2)
- VCC <3.3V>
- Audio DAC
- AVDD/VDD <3.3V>
- ETHERNET
- AVDD/DVDD <3.3V>
- PDM MIC
- High PSRR LDO
- VDD <1.8V>
- ONSEMI NCP161
- CAN
- 3.3V
- 5V
- M.2 KEY-E(SD3)
- DCDC BUCK
- VEXT_3V3
- 3.3V
- MPS MP2147
- 3.3V/4A
- IO EXP
- Load Switch
- 3.3V
- VDD_5V
- Load SW
- NXP NX5P2924 x2
- 5V
- Diode DML3006
- 5V/3A
- USB C DRP
- Load Switch
- NXP NX20P3483UK
- VBUS <5V>
- VDD <3.3V>
- RTC
- Always on LDO
- VCC <3.3V>
- TI TLV76033
sheet 17
- i.MX91 PWR
- # NVCC_BBSM_1P8: 1.8V / 2mA
- Imax = N x C x V x (0.5 x F)
- # VDD_SOC: (0.65V-0.9V)
- # VDD_xxx_0P8: 0.8V
- # VDD_xxx_1P8: 1.8V
- # VDD_USB_3P3: 3.3V
sheet 18
- 16bit LPDDR4
- # VDD1: 1.8V /400mA
- # VDD2 : 1.1V / 600mA
- # VDDQ: 1.1V/ 360mA
- LPDDR4: 1GB (x16)
- Z:85 OHM
- Z:85 OHM
- # Power Supply Voltage Sequence:
- RESET_n is held LOW.
  VDD1 >= VDD2
  VDD2 >= VDDQ-200mV
- Z:85 OHM
- Power ramp duration tINIT0 (Tb¨CTa) must not exceed 20ms.
- Close to DRAM device.
- GND test points should be put closely to
  CK, DQS, DQ, CA signal test points.
- # ZQ1 is reserved for 2CS LPDDR4
- For 100-ball LPDDR4
sheet 19
- SYS PMIC
- 1.1V/2A
- 0.6V-3.775V / 25mV
- # System Reset Button
- OD
- 0.85V/2.7A  DVS
- OD
- 0.6V-2.1875V / 12.5mV
- Sense from PMIC output for current measuring as default;
- Sense from Processor power pin when current sensing resistor is removed;
- 1.8V/2A
- 0.6V-3.775V / 25mV
- <LDO1>
- 3.3V/2.5A
- 0.6V-3.775V / 25mV
- I2C ADDR: 0x32 (011 0010x)
- Note:
- 3.3V/400mA
- 1. PMIC_RST_B is used as Cold Reset as default.
- 2. WDOG_B is used as Cold Reset, external pull up is needed for BSDL mode.
- 3. AGND is sensitive, should be separated from GND(EPAD), don't short them directly.
- PMIC: PF9453 CFG
- SEQ
- Tstep
- REGULATOR
- VOL (V)
- MAX I (mA)
- PWR RAIL
- RANGE(V)
- Req I (mA)
- Low for disable;
  High for enable, default with external PU.
- 0
- LDO_SNVS
- 1.8
- 10
- NVCC_BBSM_1P8
- 1.65-1.8-1.95
- 2
- 0.61-0.65-0.69
- VSYS pin is very senstive, should better be isolated with BUCK inputs and be connected to power input with dedicated trace.
  VSYS pin should also be decoupled separately to AGND.
- 1
- T1
- BUCK2
- 0.85
- 2700
- VDD_SOC
- 0.76-0.8-0.84
- 1500
- 0.8-0.85-0.9
- VDD_ANA_0P8
  VDD_USB_0P8
- 1.8V/10mA
- 2
- T2
- LDO2
- 0.8
- 200
- 0.76-0.8-0.9
- 200
- 0.8V-3.0V / 25mV
- VDD_ANAx_1P8
  NVCC_WAKEUP
  VDD_USB_1P8
  DDR_VDD1
  VDD_1V8
- (3.3V/1.8V)/250mA
- 0.8V-3.3V / 25mV
- 3
- T3
- BUCK3
- 1.8
- 2000
- 1.71-1.8-1.89
- 2000
- Low for 3.3V default;
  High for 1.8V.
- 0.8V/200mA
- 0.5V-1.95V / 25mV
- 4
- T4
- BUCK1
- 1.1
- 2000
- VDD2_DDR/LPD4_VDD2
- 1.06-1.1-1.14
- 1000
- NVCC_AON
  NVCC_GPIO
  VDD_USB_3P3
  VDD_3V3
- 5
- T5
- BUCK4
- 3.3
- 2500
- 3.0-3.3-3.45
- 2500
- POR_B Buffer
- PWR LED
- 6
- T5
- Load Switch
- 3.3
- 400
- VSD_3V3
- 3.3
- 400
- 7
- T6
- LDO1
- 3.3/1.8
- 250
- NVCC_SD2
- 3.3/1.8
- 150
- 8
- Tpor_b
- POR_B
- --
- --
- POR_B
- --
- --
- #BUF w/ OD
